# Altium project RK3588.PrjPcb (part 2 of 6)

## Sheet rk3588_LPDDR4.SchDoc
size C; SheetNumber: 3; SheetTotal: 22
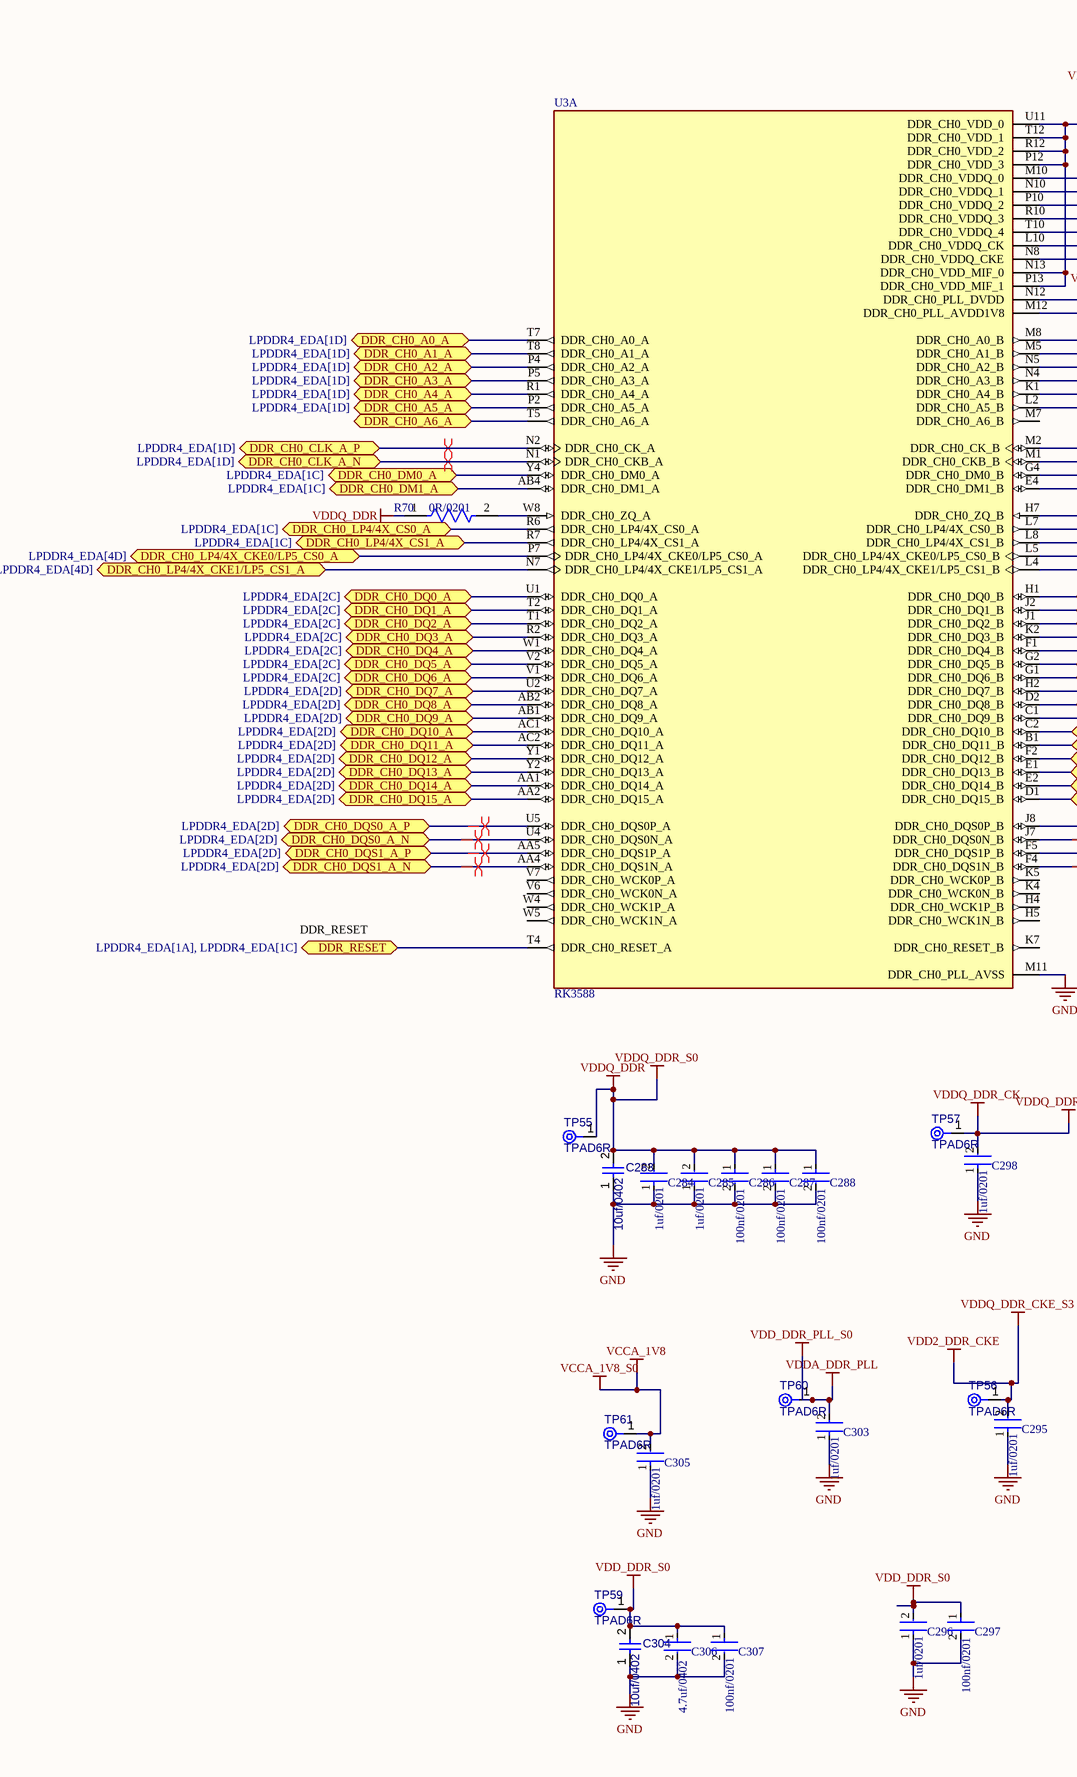
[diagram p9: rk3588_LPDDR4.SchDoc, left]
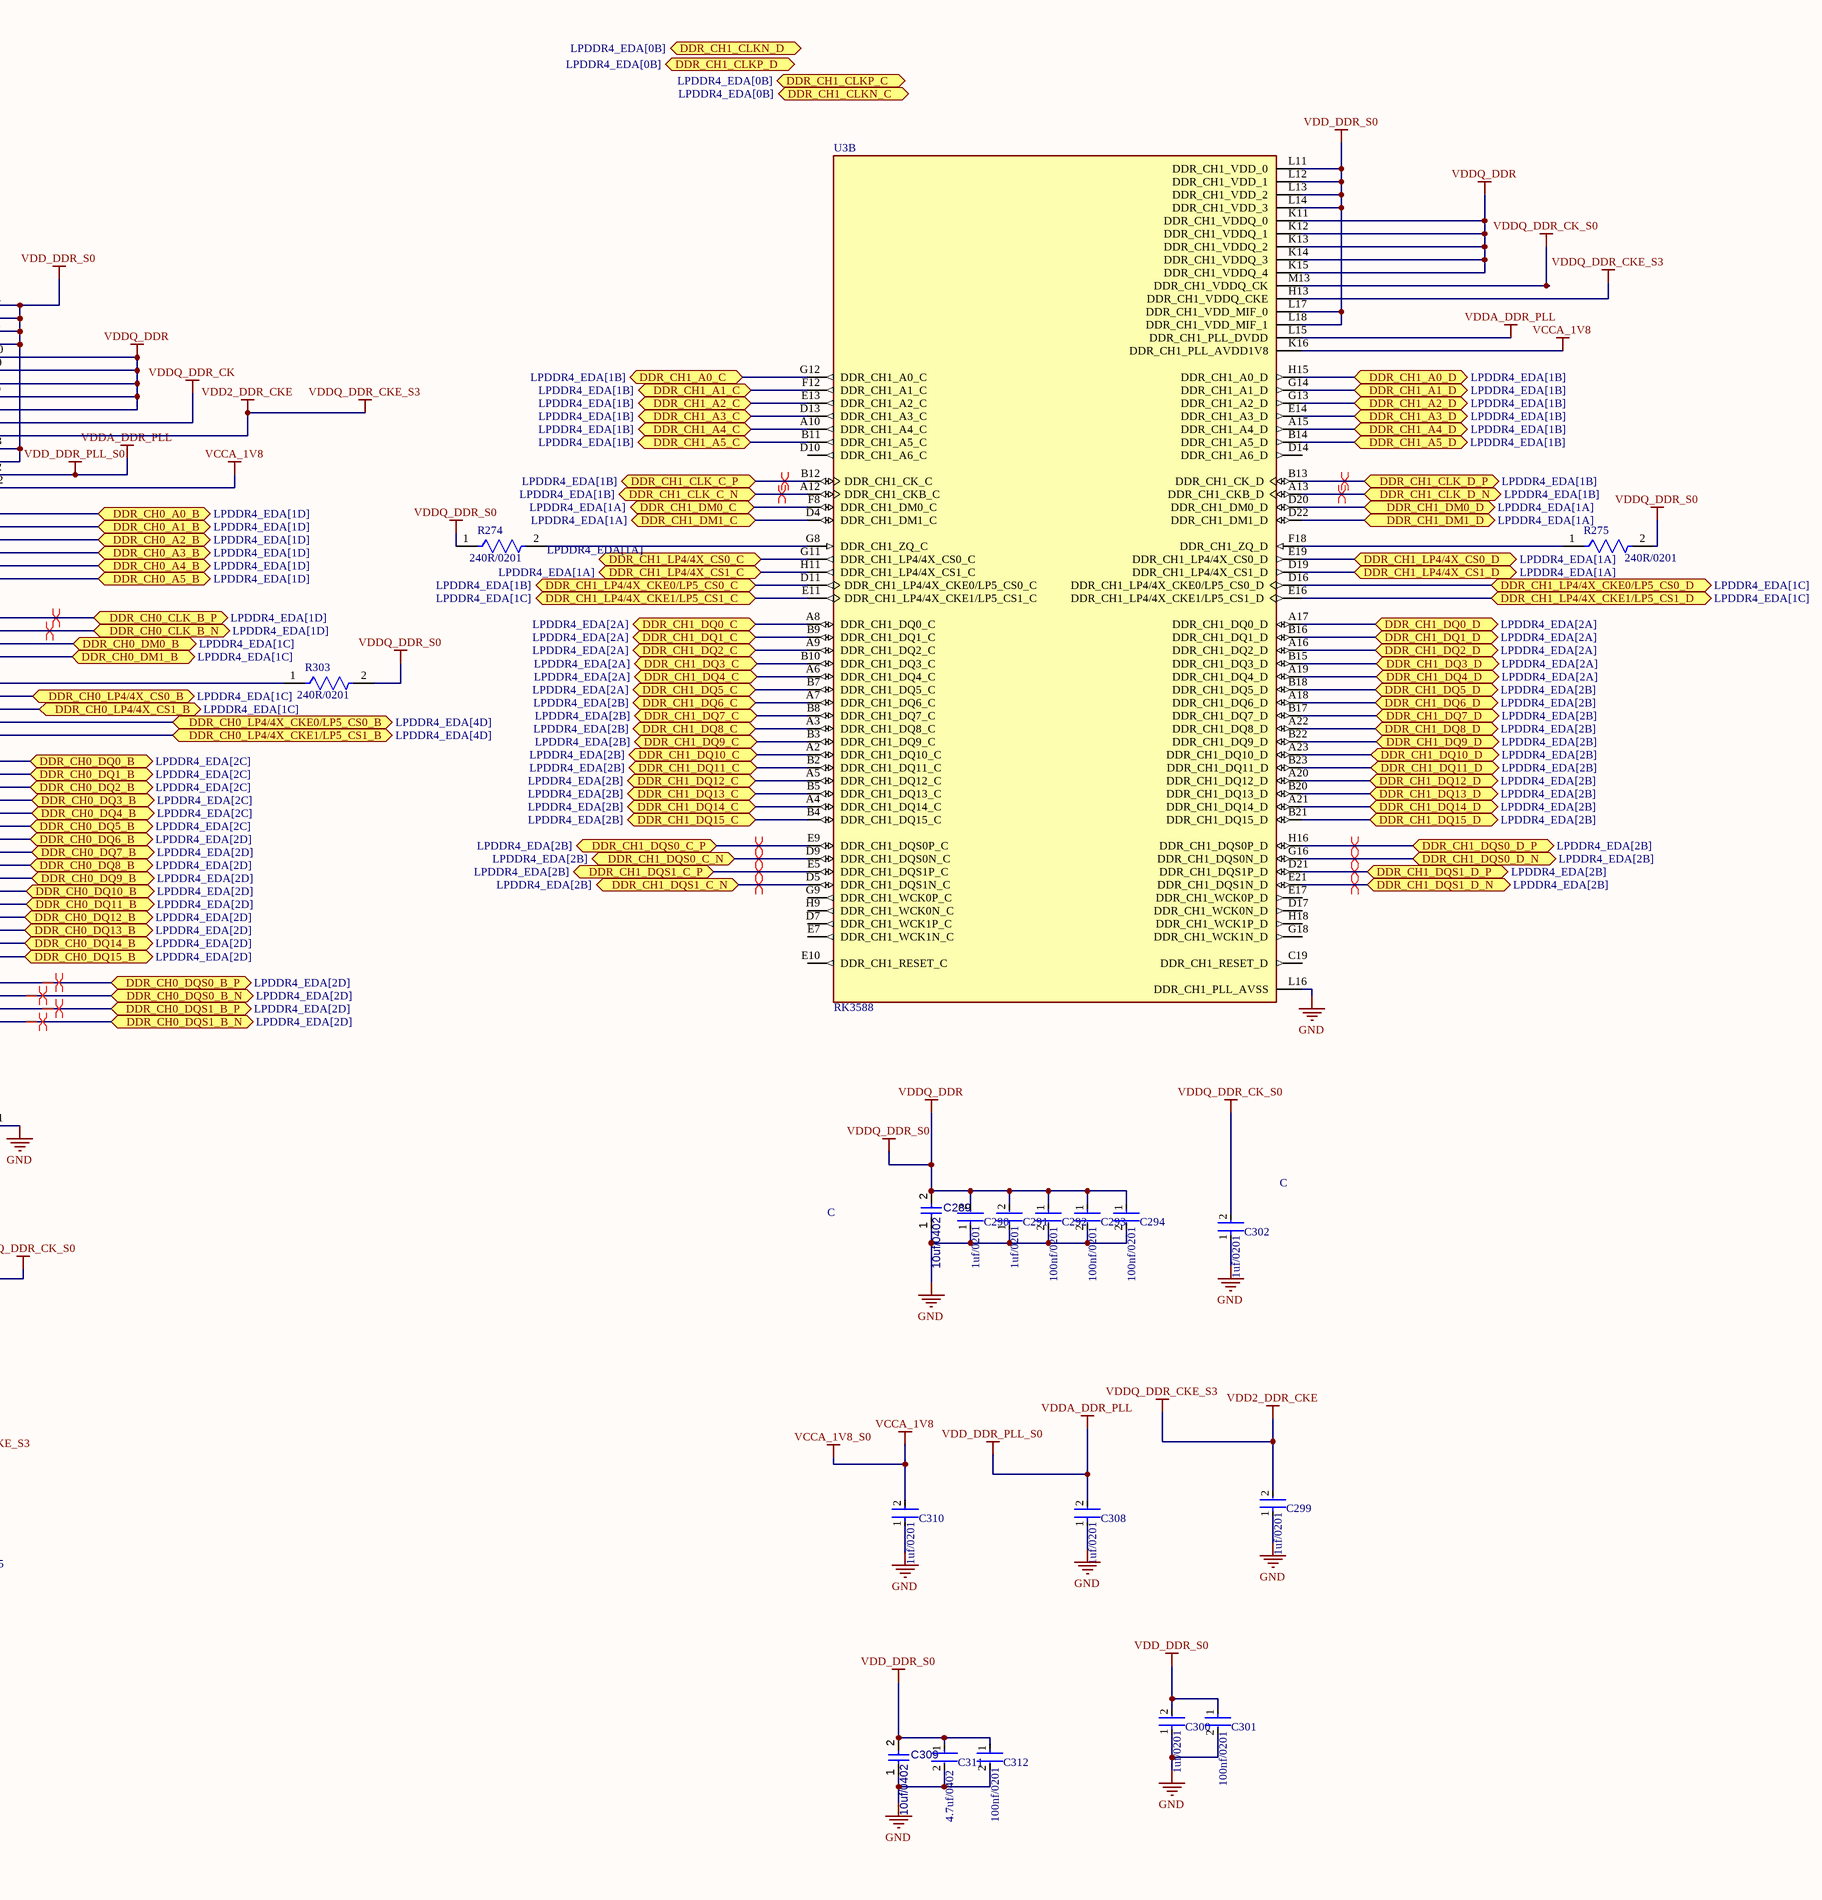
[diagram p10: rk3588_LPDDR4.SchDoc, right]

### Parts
C283  10uf/0402  [CAPC0402(1005)60_L]
C284  1uf/0201  [FP-CC0201-BA-MFG]
C285  1uf/0201  [FP-CC0201-BA-MFG]
C286  100nf/0201  [FP-CL03-IPC_C]
C287  100nf/0201  [FP-CL03-IPC_C]
C288  100nf/0201  [FP-CL03-IPC_C]
C289  10uf/0402  [CAPC0402(1005)60_L]
C290  1uf/0201  [FP-CC0201-BA-MFG]
C291  1uf/0201  [FP-CC0201-BA-MFG]
C292  100nf/0201  [FP-CL03-IPC_C]
C293  100nf/0201  [FP-CL03-IPC_C]
C294  100nf/0201  [FP-CL03-IPC_C]
C295  1uf/0201  [FP-CC0201-BA-MFG]
C296  1uf/0201  [FP-CC0201-BA-MFG]
C297  100nf/0201  [FP-CL03-IPC_C]
C298  1uf/0201  [FP-CC0201-BA-MFG]
C299  1uf/0201  [FP-CC0201-BA-MFG]
C300  1uf/0201  [FP-CC0201-BA-MFG]
C301  100nf/0201  [FP-CL03-IPC_C]
C302  1uf/0201  [FP-CC0201-BA-MFG]
C303  1uf/0201  [FP-CC0201-BA-MFG]
C304  10uf/0402  [CAPC0402(1005)60_L]
C305  1uf/0201  [FP-CC0201-BA-MFG]
C306  4.7uf/0402  [FP-CC0402-MFG]
C307  100nf/0201  [FP-CL03-IPC_C]
C308  1uf/0201  [FP-CC0201-BA-MFG]
C309  10uf/0402  [CAPC0402(1005)60_L]
C310  1uf/0201  [FP-CC0201-BA-MFG]
C311  4.7uf/0402  [FP-CC0402-MFG]
C312  100nf/0201  [FP-CL03-IPC_C]
R70  0R/0201  [FP-RMCF0201-IPC_C]
R274  240R/0201  [FP-RMCF0201-IPC_C]
R275  240R/0201  [FP-RMCF0201-IPC_C]
R303  240R/0201  [FP-RMCF0201-IPC_C]
TP55  TPAD6R  [TP06R]  (no BOM)
TP56  TPAD6R  [TP06R]  (no BOM)
TP57  TPAD6R  [TP06R]  (no BOM)
TP59  TPAD6R  [TP06R]  (no BOM)
TP60  TPAD6R  [TP06R]  (no BOM)
TP61  TPAD6R  [TP06R]  (no BOM)
U3  RK3588  [BGA1088C65P34X34_2300X2300X204N]  (parts A,B of 30)

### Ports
DDR_CH0_A0_A (bidir, see LPDDR4_EDA[1D]), DDR_CH0_A0_B (bidir, see LPDDR4_EDA[1D]), DDR_CH0_A1_A (bidir, see LPDDR4_EDA[1D]), DDR_CH0_A1_B (bidir, see LPDDR4_EDA[1D]), DDR_CH0_A2_A (bidir, see LPDDR4_EDA[1D]), DDR_CH0_A2_B (bidir, see LPDDR4_EDA[1D]), DDR_CH0_A3_A (bidir, see LPDDR4_EDA[1D]), DDR_CH0_A3_B (bidir, see LPDDR4_EDA[1D]), DDR_CH0_A4_A (bidir, see LPDDR4_EDA[1D]), DDR_CH0_A4_B (bidir, see LPDDR4_EDA[1D]), DDR_CH0_A5_A (bidir, see LPDDR4_EDA[1D]), DDR_CH0_A5_B (bidir, see LPDDR4_EDA[1D]), DDR_CH0_A6_A (bidir), DDR_CH0_CLK_A_N (bidir, see LPDDR4_EDA[1D]), DDR_CH0_CLK_A_P (bidir, see LPDDR4_EDA[1D]), DDR_CH0_CLK_B_N (bidir, see LPDDR4_EDA[1D]), DDR_CH0_CLK_B_P (bidir, see LPDDR4_EDA[1D]), DDR_CH0_DM0_A (bidir, see LPDDR4_EDA[1C]), DDR_CH0_DM0_B (bidir, see LPDDR4_EDA[1C]), DDR_CH0_DM1_A (bidir, see LPDDR4_EDA[1C]), DDR_CH0_DM1_B (bidir, see LPDDR4_EDA[1C]), DDR_CH0_DQ0_A (bidir, see LPDDR4_EDA[2C]), DDR_CH0_DQ0_B (bidir, see LPDDR4_EDA[2C]), DDR_CH0_DQ1_A (bidir, see LPDDR4_EDA[2C]), DDR_CH0_DQ1_B (bidir, see LPDDR4_EDA[2C]), DDR_CH0_DQ2_A (bidir, see LPDDR4_EDA[2C]), DDR_CH0_DQ2_B (bidir, see LPDDR4_EDA[2C]), DDR_CH0_DQ3_A (bidir, see LPDDR4_EDA[2C]), DDR_CH0_DQ3_B (bidir, see LPDDR4_EDA[2C]), DDR_CH0_DQ4_A (bidir, see LPDDR4_EDA[2C]), DDR_CH0_DQ4_B (bidir, see LPDDR4_EDA[2C]), DDR_CH0_DQ5_A (bidir, see LPDDR4_EDA[2C]), DDR_CH0_DQ5_B (bidir, see LPDDR4_EDA[2C]), DDR_CH0_DQ6_A (bidir, see LPDDR4_EDA[2C]), DDR_CH0_DQ6_B (bidir, see LPDDR4_EDA[2D]), DDR_CH0_DQ7_A (bidir, see LPDDR4_EDA[2D]), DDR_CH0_DQ7_B (bidir, see LPDDR4_EDA[2D]), DDR_CH0_DQ8_A (bidir, see LPDDR4_EDA[2D]), DDR_CH0_DQ8_B (bidir, see LPDDR4_EDA[2D]), DDR_CH0_DQ9_A (bidir, see LPDDR4_EDA[2D]), DDR_CH0_DQ9_B (bidir, see LPDDR4_EDA[2D]), DDR_CH0_DQ10_A (bidir, see LPDDR4_EDA[2D]), DDR_CH0_DQ10_B (bidir, see LPDDR4_EDA[2D]), DDR_CH0_DQ11_A (bidir, see LPDDR4_EDA[2D]), DDR_CH0_DQ11_B (bidir, see LPDDR4_EDA[2D]), DDR_CH0_DQ12_A (bidir, see LPDDR4_EDA[2D]), DDR_CH0_DQ12_B (bidir, see LPDDR4_EDA[2D]), DDR_CH0_DQ13_A (bidir, see LPDDR4_EDA[2D]), DDR_CH0_DQ13_B (bidir, see LPDDR4_EDA[2D]), DDR_CH0_DQ14_A (bidir, see LPDDR4_EDA[2D]), DDR_CH0_DQ14_B (bidir, see LPDDR4_EDA[2D]), DDR_CH0_DQ15_A (bidir, see LPDDR4_EDA[2D]), DDR_CH0_DQ15_B (bidir, see LPDDR4_EDA[2D]), DDR_CH0_DQS0_A_N (bidir, see LPDDR4_EDA[2D]), DDR_CH0_DQS0_A_P (bidir, see LPDDR4_EDA[2D]), DDR_CH0_DQS0_B_N (bidir, see LPDDR4_EDA[2D]), DDR_CH0_DQS0_B_P (bidir, see LPDDR4_EDA[2D]), DDR_CH0_DQS1_A_N (bidir, see LPDDR4_EDA[2D]), DDR_CH0_DQS1_A_P (bidir, see LPDDR4_EDA[2D]), DDR_CH0_DQS1_B_N (bidir, see LPDDR4_EDA[2D]), DDR_CH0_DQS1_B_P (bidir, see LPDDR4_EDA[2D]), DDR_CH0_LP4/4X_CKE0/LP5_CS0_A (bidir, see LPDDR4_EDA[4D]), DDR_CH0_LP4/4X_CKE0/LP5_CS0_B (bidir, see LPDDR4_EDA[4D]), DDR_CH0_LP4/4X_CKE1/LP5_CS1_A (bidir, see LPDDR4_EDA[4D]), DDR_CH0_LP4/4X_CKE1/LP5_CS1_B (bidir, see LPDDR4_EDA[4D]), DDR_CH0_LP4/4X_CS0_A (bidir, see LPDDR4_EDA[1C]), DDR_CH0_LP4/4X_CS0_B (bidir, see LPDDR4_EDA[1C]), DDR_CH0_LP4/4X_CS1_A (bidir, see LPDDR4_EDA[1C]), DDR_CH0_LP4/4X_CS1_B (bidir, see LPDDR4_EDA[1C]), DDR_CH1_A0_C (bidir, see LPDDR4_EDA[1B]), DDR_CH1_A0_D (bidir, see LPDDR4_EDA[1B]), DDR_CH1_A1_C (bidir, see LPDDR4_EDA[1B]), DDR_CH1_A1_D (bidir, see LPDDR4_EDA[1B]), DDR_CH1_A2_C (bidir, see LPDDR4_EDA[1B]), DDR_CH1_A2_D (bidir, see LPDDR4_EDA[1B]), DDR_CH1_A3_C (bidir, see LPDDR4_EDA[1B]), DDR_CH1_A3_D (bidir, see LPDDR4_EDA[1B]), DDR_CH1_A4_C (bidir, see LPDDR4_EDA[1B]), DDR_CH1_A4_D (bidir, see LPDDR4_EDA[1B]), DDR_CH1_A5_C (bidir, see LPDDR4_EDA[1B]), DDR_CH1_A5_D (bidir, see LPDDR4_EDA[1B]), DDR_CH1_CLK_C_N (bidir, see LPDDR4_EDA[1B]), DDR_CH1_CLK_C_P (bidir, see LPDDR4_EDA[1B]), DDR_CH1_CLK_D_N (bidir, see LPDDR4_EDA[1B]), DDR_CH1_CLK_D_P (bidir, see LPDDR4_EDA[1B]), DDR_CH1_CLKN_C (bidir, see LPDDR4_EDA[0B]), DDR_CH1_CLKN_D (bidir, see LPDDR4_EDA[0B]), DDR_CH1_CLKP_C (bidir, see LPDDR4_EDA[0B]), DDR_CH1_CLKP_D (bidir, see LPDDR4_EDA[0B]), DDR_CH1_DM0_C (bidir, see LPDDR4_EDA[1A]), DDR_CH1_DM0_D (bidir, see LPDDR4_EDA[1A]), DDR_CH1_DM1_C (bidir, see LPDDR4_EDA[1A]), DDR_CH1_DM1_D (bidir, see LPDDR4_EDA[1A]), DDR_CH1_DQ0_C (bidir, see LPDDR4_EDA[2A]), DDR_CH1_DQ0_D (bidir, see LPDDR4_EDA[2A]), DDR_CH1_DQ1_C (bidir, see LPDDR4_EDA[2A]), DDR_CH1_DQ1_D (bidir, see LPDDR4_EDA[2A]), DDR_CH1_DQ2_C (bidir, see LPDDR4_EDA[2A]), DDR_CH1_DQ2_D (bidir, see LPDDR4_EDA[2A]), DDR_CH1_DQ3_C (bidir, see LPDDR4_EDA[2A]), DDR_CH1_DQ3_D (bidir, see LPDDR4_EDA[2A]), DDR_CH1_DQ4_C (bidir, see LPDDR4_EDA[2A]), DDR_CH1_DQ4_D (bidir, see LPDDR4_EDA[2A]), DDR_CH1_DQ5_C (bidir, see LPDDR4_EDA[2A]), DDR_CH1_DQ5_D (bidir, see LPDDR4_EDA[2B]), DDR_CH1_DQ6_C (bidir, see LPDDR4_EDA[2B]), DDR_CH1_DQ6_D (bidir, see LPDDR4_EDA[2B]), DDR_CH1_DQ7_C (bidir, see LPDDR4_EDA[2B]), DDR_CH1_DQ7_D (bidir, see LPDDR4_EDA[2B]), DDR_CH1_DQ8_C (bidir, see LPDDR4_EDA[2B]), DDR_CH1_DQ8_D (bidir, see LPDDR4_EDA[2B]), DDR_CH1_DQ9_C (bidir, see LPDDR4_EDA[2B]), DDR_CH1_DQ9_D (bidir, see LPDDR4_EDA[2B]), DDR_CH1_DQ10_C (bidir, see LPDDR4_EDA[2B]), DDR_CH1_DQ10_D (bidir, see LPDDR4_EDA[2B]), DDR_CH1_DQ11_C (bidir, see LPDDR4_EDA[2B]), DDR_CH1_DQ11_D (bidir, see LPDDR4_EDA[2B]), DDR_CH1_DQ12_C (bidir, see LPDDR4_EDA[2B]), DDR_CH1_DQ12_D (bidir, see LPDDR4_EDA[2B]), DDR_CH1_DQ13_C (bidir, see LPDDR4_EDA[2B]), DDR_CH1_DQ13_D (bidir, see LPDDR4_EDA[2B]), DDR_CH1_DQ14_C (bidir, see LPDDR4_EDA[2B]), DDR_CH1_DQ14_D (bidir, see LPDDR4_EDA[2B]), DDR_CH1_DQ15_C (bidir, see LPDDR4_EDA[2B]), DDR_CH1_DQ15_D (bidir, see LPDDR4_EDA[2B]), DDR_CH1_DQS0_C_N (bidir, see LPDDR4_EDA[2B]), DDR_CH1_DQS0_C_P (bidir, see LPDDR4_EDA[2B]), DDR_CH1_DQS0_D_N (bidir, see LPDDR4_EDA[2B]), DDR_CH1_DQS0_D_P (bidir, see LPDDR4_EDA[2B]), DDR_CH1_DQS1_C_N (bidir, see LPDDR4_EDA[2B]), DDR_CH1_DQS1_C_P (bidir, see LPDDR4_EDA[2B]), DDR_CH1_DQS1_D_N (bidir, see LPDDR4_EDA[2B]), DDR_CH1_DQS1_D_P (bidir, see LPDDR4_EDA[2B]), DDR_CH1_LP4/4X_CKE0/LP5_CS0_C (bidir, see LPDDR4_EDA[1B]), DDR_CH1_LP4/4X_CKE0/LP5_CS0_D (bidir, see LPDDR4_EDA[1C]), DDR_CH1_LP4/4X_CKE1/LP5_CS1_C (bidir, see LPDDR4_EDA[1C]), DDR_CH1_LP4/4X_CKE1/LP5_CS1_D (bidir, see LPDDR4_EDA[1C]), DDR_CH1_LP4/4X_CS0_C (bidir, see LPDDR4_EDA[1A]), DDR_CH1_LP4/4X_CS0_D (bidir, see LPDDR4_EDA[1A]), DDR_CH1_LP4/4X_CS1_C (bidir, see LPDDR4_EDA[1A]), DDR_CH1_LP4/4X_CS1_D (bidir, see LPDDR4_EDA[1A]), DDR_RESET (bidir, see LPDDR4_EDA[1A], LPDDR4_EDA[1C])

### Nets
GND: C283.1 C284.1 C285.1 C286.2 C287.2 C288.2 C289.1 C290.1 C291.1 C292.2 C293.2 C294.2 C295.1 C296.1 C297.2 C298.1 C299.1 C300.1 C301.2 C302.1 C303.1 C304.1 C305.1 C306.2 C307.2 C308.1 C309.1 C310.1 C311.2 C312.2 U3.L16(DDR_CH1_PLL_AVSS) U3.M11(DDR_CH0_PLL_AVSS)
VCCA_1V8: C305.2 C310.2 TP61.1(TP) U3.K16(DDR_CH1_PLL_AVDD1V8) U3.M12(DDR_CH0_PLL_AVDD1V8)  [also labelled VCCA_1V8_S0]
VDD2_DDR_CKE: C295.2 C299.2 TP56.1(TP) U3.H13(DDR_CH1_VDDQ_CKE) U3.N8(DDR_CH0_VDDQ_CKE)  [also labelled VDDQ_DDR_CKE_S3]
VDD_DDR_PLL_S0: C303.2 C308.2 TP60.1(TP) U3.L15(DDR_CH1_PLL_DVDD) U3.N12(DDR_CH0_PLL_DVDD)  [also labelled VDDA_DDR_PLL]  [project net NLDO2]
VDD_DDR_S0: C296.2 C297.1 C300.2 C301.1 C304.2 C306.1 C307.1 C309.2 C311.1 C312.1 TP59.1(TP) U3.L11(DDR_CH1_VDD_0) U3.L12(DDR_CH1_VDD_1) U3.L13(DDR_CH1_VDD_2) U3.L14(DDR_CH1_VDD_3) U3.L17(DDR_CH1_VDD_MIF_0) U3.L18(DDR_CH1_VDD_MIF_1) U3.N13(DDR_CH0_VDD_MIF_0) U3.P12(DDR_CH0_VDD_3) U3.P13(DDR_CH0_VDD_MIF_1) U3.R12(DDR_CH0_VDD_2) U3.T12(DDR_CH0_VDD_1) U3.U11(DDR_CH0_VDD_0)
VDDQ_DDR: C283.2 C284.2 C285.2 C286.1 C287.1 C288.1 C289.2 C290.2 C291.2 C292.1 C293.1 C294.1 R70.1 R274.1 R275.2 R303.2 TP55.1(TP) U3.K11(DDR_CH1_VDDQ_0) U3.K12(DDR_CH1_VDDQ_1) U3.K13(DDR_CH1_VDDQ_2) U3.K14(DDR_CH1_VDDQ_3) U3.K15(DDR_CH1_VDDQ_4) U3.M10(DDR_CH0_VDDQ_0) U3.N10(DDR_CH0_VDDQ_1) U3.P10(DDR_CH0_VDDQ_2) U3.R10(DDR_CH0_VDDQ_3) U3.T10(DDR_CH0_VDDQ_4)  [also labelled VDDQ_DDR_S0]  [project net VOUT9]
VDDQ_DDR_CK: C298.2 C302.2 TP57.1(TP) U3.L10(DDR_CH0_VDDQ_CK) U3.M13(DDR_CH1_VDDQ_CK)  [also labelled VDDQ_DDR_CK_S0]
DDR_CH0_A0_A: U3.T7(DDR_CH0_A0_A) ; port DDR_CH0_A0_A
DDR_CH0_A0_B: U3.M8(DDR_CH0_A0_B) ; port DDR_CH0_A0_B
DDR_CH0_A1_A: U3.T8(DDR_CH0_A1_A) ; port DDR_CH0_A1_A
DDR_CH0_A1_B: U3.M5(DDR_CH0_A1_B) ; port DDR_CH0_A1_B
DDR_CH0_A2_A: U3.P4(DDR_CH0_A2_A) ; port DDR_CH0_A2_A
DDR_CH0_A2_B: U3.N5(DDR_CH0_A2_B) ; port DDR_CH0_A2_B
DDR_CH0_A3_A: U3.P5(DDR_CH0_A3_A) ; port DDR_CH0_A3_A
DDR_CH0_A3_B: U3.N4(DDR_CH0_A3_B) ; port DDR_CH0_A3_B
DDR_CH0_A4_A: U3.R1(DDR_CH0_A4_A) ; port DDR_CH0_A4_A
DDR_CH0_A4_B: U3.K1(DDR_CH0_A4_B) ; port DDR_CH0_A4_B
DDR_CH0_A5_A: U3.P2(DDR_CH0_A5_A) ; port DDR_CH0_A5_A
DDR_CH0_A5_B: U3.L2(DDR_CH0_A5_B) ; port DDR_CH0_A5_B
DDR_CH0_A6_A: U3.T5(DDR_CH0_A6_A) ; port DDR_CH0_A6_A
DDR_CH0_CLK_A_N: U3.N1(DDR_CH0_CKB_A) ; port DDR_CH0_CLK_A_N
DDR_CH0_CLK_A_P: U3.N2(DDR_CH0_CK_A) ; port DDR_CH0_CLK_A_P
DDR_CH0_CLK_B_N: U3.M1(DDR_CH0_CKB_B) ; port DDR_CH0_CLK_B_N
DDR_CH0_CLK_B_P: U3.M2(DDR_CH0_CK_B) ; port DDR_CH0_CLK_B_P
DDR_CH0_DM0_A: U3.Y4(DDR_CH0_DM0_A) ; port DDR_CH0_DM0_A
DDR_CH0_DM0_B: U3.G4(DDR_CH0_DM0_B) ; port DDR_CH0_DM0_B
DDR_CH0_DM1_A: U3.AB4(DDR_CH0_DM1_A) ; port DDR_CH0_DM1_A
DDR_CH0_DM1_B: U3.E4(DDR_CH0_DM1_B) ; port DDR_CH0_DM1_B
DDR_CH0_DQ0_A: U3.U1(DDR_CH0_DQ0_A) ; port DDR_CH0_DQ0_A
DDR_CH0_DQ0_B: U3.H1(DDR_CH0_DQ0_B) ; port DDR_CH0_DQ0_B
DDR_CH0_DQ1_A: U3.T2(DDR_CH0_DQ1_A) ; port DDR_CH0_DQ1_A
DDR_CH0_DQ1_B: U3.J2(DDR_CH0_DQ1_B) ; port DDR_CH0_DQ1_B
DDR_CH0_DQ2_A: U3.T1(DDR_CH0_DQ2_A) ; port DDR_CH0_DQ2_A
DDR_CH0_DQ2_B: U3.J1(DDR_CH0_DQ2_B) ; port DDR_CH0_DQ2_B
DDR_CH0_DQ3_A: U3.R2(DDR_CH0_DQ3_A) ; port DDR_CH0_DQ3_A
DDR_CH0_DQ3_B: U3.K2(DDR_CH0_DQ3_B) ; port DDR_CH0_DQ3_B
DDR_CH0_DQ4_A: U3.W1(DDR_CH0_DQ4_A) ; port DDR_CH0_DQ4_A
DDR_CH0_DQ4_B: U3.F1(DDR_CH0_DQ4_B) ; port DDR_CH0_DQ4_B
DDR_CH0_DQ5_A: U3.V2(DDR_CH0_DQ5_A) ; port DDR_CH0_DQ5_A
DDR_CH0_DQ5_B: U3.G2(DDR_CH0_DQ5_B) ; port DDR_CH0_DQ5_B
DDR_CH0_DQ6_A: U3.V1(DDR_CH0_DQ6_A) ; port DDR_CH0_DQ6_A
DDR_CH0_DQ6_B: U3.G1(DDR_CH0_DQ6_B) ; port DDR_CH0_DQ6_B
DDR_CH0_DQ7_A: U3.U2(DDR_CH0_DQ7_A) ; port DDR_CH0_DQ7_A
DDR_CH0_DQ7_B: U3.H2(DDR_CH0_DQ7_B) ; port DDR_CH0_DQ7_B
DDR_CH0_DQ8_A: U3.AB2(DDR_CH0_DQ8_A) ; port DDR_CH0_DQ8_A
DDR_CH0_DQ8_B: U3.D2(DDR_CH0_DQ8_B) ; port DDR_CH0_DQ8_B
DDR_CH0_DQ9_A: U3.AB1(DDR_CH0_DQ9_A) ; port DDR_CH0_DQ9_A
DDR_CH0_DQ9_B: U3.C1(DDR_CH0_DQ9_B) ; port DDR_CH0_DQ9_B
DDR_CH0_DQ10_A: U3.AC1(DDR_CH0_DQ10_A) ; port DDR_CH0_DQ10_A
DDR_CH0_DQ10_B: U3.C2(DDR_CH0_DQ10_B) ; port DDR_CH0_DQ10_B
DDR_CH0_DQ11_A: U3.AC2(DDR_CH0_DQ11_A) ; port DDR_CH0_DQ11_A
DDR_CH0_DQ11_B: U3.B1(DDR_CH0_DQ11_B) ; port DDR_CH0_DQ11_B
DDR_CH0_DQ12_A: U3.Y1(DDR_CH0_DQ12_A) ; port DDR_CH0_DQ12_A
DDR_CH0_DQ12_B: U3.F2(DDR_CH0_DQ12_B) ; port DDR_CH0_DQ12_B
DDR_CH0_DQ13_A: U3.Y2(DDR_CH0_DQ13_A) ; port DDR_CH0_DQ13_A
DDR_CH0_DQ13_B: U3.E1(DDR_CH0_DQ13_B) ; port DDR_CH0_DQ13_B
DDR_CH0_DQ14_A: U3.AA1(DDR_CH0_DQ14_A) ; port DDR_CH0_DQ14_A
DDR_CH0_DQ14_B: U3.E2(DDR_CH0_DQ14_B) ; port DDR_CH0_DQ14_B
DDR_CH0_DQ15_A: U3.AA2(DDR_CH0_DQ15_A) ; port DDR_CH0_DQ15_A
DDR_CH0_DQ15_B: U3.D1(DDR_CH0_DQ15_B) ; port DDR_CH0_DQ15_B
DDR_CH0_DQS0_A_N: U3.U4(DDR_CH0_DQS0N_A) ; port DDR_CH0_DQS0_A_N
DDR_CH0_DQS0_A_P: U3.U5(DDR_CH0_DQS0P_A) ; port DDR_CH0_DQS0_A_P
DDR_CH0_DQS0_B_N: U3.J7(DDR_CH0_DQS0N_B) ; port DDR_CH0_DQS0_B_N
DDR_CH0_DQS0_B_P: U3.J8(DDR_CH0_DQS0P_B) ; port DDR_CH0_DQS0_B_P
DDR_CH0_DQS1_A_N: U3.AA4(DDR_CH0_DQS1N_A) ; port DDR_CH0_DQS1_A_N
DDR_CH0_DQS1_A_P: U3.AA5(DDR_CH0_DQS1P_A) ; port DDR_CH0_DQS1_A_P
DDR_CH0_DQS1_B_N: U3.F4(DDR_CH0_DQS1N_B) ; port DDR_CH0_DQS1_B_N
DDR_CH0_DQS1_B_P: U3.F5(DDR_CH0_DQS1P_B) ; port DDR_CH0_DQS1_B_P
DDR_CH0_LP4/4X_CKE0/LP5_CS0_A: U3.P7(DDR_CH0_LP4/4X_CKE0/LP5_CS0_A) ; port DDR_CH0_LP4/4X_CKE0/LP5_CS0_A
DDR_CH0_LP4/4X_CKE0/LP5_CS0_B: U3.L5(DDR_CH0_LP4/4X_CKE0/LP5_CS0_B) ; port DDR_CH0_LP4/4X_CKE0/LP5_CS0_B
DDR_CH0_LP4/4X_CKE1/LP5_CS1_A: U3.N7(DDR_CH0_LP4/4X_CKE1/LP5_CS1_A) ; port DDR_CH0_LP4/4X_CKE1/LP5_CS1_A
DDR_CH0_LP4/4X_CKE1/LP5_CS1_B: U3.L4(DDR_CH0_LP4/4X_CKE1/LP5_CS1_B) ; port DDR_CH0_LP4/4X_CKE1/LP5_CS1_B
DDR_CH0_LP4/4X_CS0_A: U3.R6(DDR_CH0_LP4/4X_CS0_A) ; port DDR_CH0_LP4/4X_CS0_A
DDR_CH0_LP4/4X_CS0_B: U3.L7(DDR_CH0_LP4/4X_CS0_B) ; port DDR_CH0_LP4/4X_CS0_B
DDR_CH0_LP4/4X_CS1_A: U3.R7(DDR_CH0_LP4/4X_CS1_A) ; port DDR_CH0_LP4/4X_CS1_A
DDR_CH0_LP4/4X_CS1_B: U3.L8(DDR_CH0_LP4/4X_CS1_B) ; port DDR_CH0_LP4/4X_CS1_B
DDR_CH1_A0_C: U3.G12(DDR_CH1_A0_C) ; port DDR_CH1_A0_C
DDR_CH1_A0_D: U3.H15(DDR_CH1_A0_D) ; port DDR_CH1_A0_D
DDR_CH1_A1_C: U3.F12(DDR_CH1_A1_C) ; port DDR_CH1_A1_C
DDR_CH1_A1_D: U3.G14(DDR_CH1_A1_D) ; port DDR_CH1_A1_D
DDR_CH1_A2_C: U3.E13(DDR_CH1_A2_C) ; port DDR_CH1_A2_C
DDR_CH1_A2_D: U3.G13(DDR_CH1_A2_D) ; port DDR_CH1_A2_D
DDR_CH1_A3_C: U3.D13(DDR_CH1_A3_C) ; port DDR_CH1_A3_C
DDR_CH1_A3_D: U3.E14(DDR_CH1_A3_D) ; port DDR_CH1_A3_D
DDR_CH1_A4_C: U3.A10(DDR_CH1_A4_C) ; port DDR_CH1_A4_C
DDR_CH1_A4_D: U3.A15(DDR_CH1_A4_D) ; port DDR_CH1_A4_D
DDR_CH1_A5_C: U3.B11(DDR_CH1_A5_C) ; port DDR_CH1_A5_C
DDR_CH1_A5_D: U3.B14(DDR_CH1_A5_D) ; port DDR_CH1_A5_D
DDR_CH1_CLK_C_N: U3.A12(DDR_CH1_CKB_C) ; port DDR_CH1_CLK_C_N
DDR_CH1_CLK_C_P: U3.B12(DDR_CH1_CK_C) ; port DDR_CH1_CLK_C_P
DDR_CH1_CLK_D_N: U3.A13(DDR_CH1_CKB_D) ; port DDR_CH1_CLK_D_N
DDR_CH1_CLK_D_P: U3.B13(DDR_CH1_CK_D) ; port DDR_CH1_CLK_D_P
DDR_CH1_DM0_C: U3.F8(DDR_CH1_DM0_C) ; port DDR_CH1_DM0_C
DDR_CH1_DM0_D: U3.D20(DDR_CH1_DM0_D) ; port DDR_CH1_DM0_D
DDR_CH1_DM1_C: U3.D4(DDR_CH1_DM1_C) ; port DDR_CH1_DM1_C
DDR_CH1_DM1_D: U3.D22(DDR_CH1_DM1_D) ; port DDR_CH1_DM1_D
DDR_CH1_DQ0_C: U3.A8(DDR_CH1_DQ0_C) ; port DDR_CH1_DQ0_C
DDR_CH1_DQ0_D: U3.A17(DDR_CH1_DQ0_D) ; port DDR_CH1_DQ0_D
DDR_CH1_DQ1_C: U3.B9(DDR_CH1_DQ1_C) ; port DDR_CH1_DQ1_C
DDR_CH1_DQ1_D: U3.B16(DDR_CH1_DQ1_D) ; port DDR_CH1_DQ1_D
DDR_CH1_DQ2_C: U3.A9(DDR_CH1_DQ2_C) ; port DDR_CH1_DQ2_C
DDR_CH1_DQ2_D: U3.A16(DDR_CH1_DQ2_D) ; port DDR_CH1_DQ2_D
DDR_CH1_DQ3_C: U3.B10(DDR_CH1_DQ3_C) ; port DDR_CH1_DQ3_C
DDR_CH1_DQ3_D: U3.B15(DDR_CH1_DQ3_D) ; port DDR_CH1_DQ3_D
DDR_CH1_DQ4_C: U3.A6(DDR_CH1_DQ4_C) ; port DDR_CH1_DQ4_C
DDR_CH1_DQ4_D: U3.A19(DDR_CH1_DQ4_D) ; port DDR_CH1_DQ4_D
DDR_CH1_DQ5_C: U3.B7(DDR_CH1_DQ5_C) ; port DDR_CH1_DQ5_C
DDR_CH1_DQ5_D: U3.B18(DDR_CH1_DQ5_D) ; port DDR_CH1_DQ5_D
DDR_CH1_DQ6_C: U3.A7(DDR_CH1_DQ6_C) ; port DDR_CH1_DQ6_C
DDR_CH1_DQ6_D: U3.A18(DDR_CH1_DQ6_D) ; port DDR_CH1_DQ6_D
DDR_CH1_DQ7_C: U3.B8(DDR_CH1_DQ7_C) ; port DDR_CH1_DQ7_C
DDR_CH1_DQ7_D: U3.B17(DDR_CH1_DQ7_D) ; port DDR_CH1_DQ7_D
DDR_CH1_DQ8_C: U3.A3(DDR_CH1_DQ8_C) ; port DDR_CH1_DQ8_C
DDR_CH1_DQ8_D: U3.A22(DDR_CH1_DQ8_D) ; port DDR_CH1_DQ8_D
DDR_CH1_DQ9_C: U3.B3(DDR_CH1_DQ9_C) ; port DDR_CH1_DQ9_C
DDR_CH1_DQ9_D: U3.B22(DDR_CH1_DQ9_D) ; port DDR_CH1_DQ9_D
DDR_CH1_DQ10_C: U3.A2(DDR_CH1_DQ10_C) ; port DDR_CH1_DQ10_C
DDR_CH1_DQ10_D: U3.A23(DDR_CH1_DQ10_D) ; port DDR_CH1_DQ10_D
DDR_CH1_DQ11_C: U3.B2(DDR_CH1_DQ11_C) ; port DDR_CH1_DQ11_C
DDR_CH1_DQ11_D: U3.B23(DDR_CH1_DQ11_D) ; port DDR_CH1_DQ11_D
DDR_CH1_DQ12_C: U3.A5(DDR_CH1_DQ12_C) ; port DDR_CH1_DQ12_C
DDR_CH1_DQ12_D: U3.A20(DDR_CH1_DQ12_D) ; port DDR_CH1_DQ12_D
DDR_CH1_DQ13_C: U3.B5(DDR_CH1_DQ13_C) ; port DDR_CH1_DQ13_C
DDR_CH1_DQ13_D: U3.B20(DDR_CH1_DQ13_D) ; port DDR_CH1_DQ13_D
DDR_CH1_DQ14_C: U3.A4(DDR_CH1_DQ14_C) ; port DDR_CH1_DQ14_C
DDR_CH1_DQ14_D: U3.A21(DDR_CH1_DQ14_D) ; port DDR_CH1_DQ14_D
DDR_CH1_DQ15_C: U3.B4(DDR_CH1_DQ15_C) ; port DDR_CH1_DQ15_C
DDR_CH1_DQ15_D: U3.B21(DDR_CH1_DQ15_D) ; port DDR_CH1_DQ15_D
DDR_CH1_DQS0_C_N: U3.D9(DDR_CH1_DQS0N_C) ; port DDR_CH1_DQS0_C_N
DDR_CH1_DQS0_C_P: U3.E9(DDR_CH1_DQS0P_C) ; port DDR_CH1_DQS0_C_P
DDR_CH1_DQS0_D_N: U3.G16(DDR_CH1_DQS0N_D) ; port DDR_CH1_DQS0_D_N
DDR_CH1_DQS0_D_P: U3.H16(DDR_CH1_DQS0P_D) ; port DDR_CH1_DQS0_D_P
DDR_CH1_DQS1_C_N: U3.D5(DDR_CH1_DQS1N_C) ; port DDR_CH1_DQS1_C_N
DDR_CH1_DQS1_C_P: U3.E5(DDR_CH1_DQS1P_C) ; port DDR_CH1_DQS1_C_P
DDR_CH1_DQS1_D_N: U3.E21(DDR_CH1_DQS1N_D) ; port DDR_CH1_DQS1_D_N
DDR_CH1_DQS1_D_P: U3.D21(DDR_CH1_DQS1P_D) ; port DDR_CH1_DQS1_D_P
DDR_CH1_LP4/4X_CKE0/LP5_CS0_C: U3.D11(DDR_CH1_LP4/4X_CKE0/LP5_CS0_C) ; port DDR_CH1_LP4/4X_CKE0/LP5_CS0_C
DDR_CH1_LP4/4X_CKE0/LP5_CS0_D: U3.D16(DDR_CH1_LP4/4X_CKE0/LP5_CS0_D) ; port DDR_CH1_LP4/4X_CKE0/LP5_CS0_D
DDR_CH1_LP4/4X_CKE1/LP5_CS1_C: U3.E11(DDR_CH1_LP4/4X_CKE1/LP5_CS1_C) ; port DDR_CH1_LP4/4X_CKE1/LP5_CS1_C
DDR_CH1_LP4/4X_CKE1/LP5_CS1_D: U3.E16(DDR_CH1_LP4/4X_CKE1/LP5_CS1_D) ; port DDR_CH1_LP4/4X_CKE1/LP5_CS1_D
DDR_CH1_LP4/4X_CS0_C: U3.G11(DDR_CH1_LP4/4X_CS0_C) ; port DDR_CH1_LP4/4X_CS0_C
DDR_CH1_LP4/4X_CS0_D: U3.E19(DDR_CH1_LP4/4X_CS0_D) ; port DDR_CH1_LP4/4X_CS0_D
DDR_CH1_LP4/4X_CS1_C: U3.H11(DDR_CH1_LP4/4X_CS1_C) ; port DDR_CH1_LP4/4X_CS1_C
DDR_CH1_LP4/4X_CS1_D: U3.D19(DDR_CH1_LP4/4X_CS1_D) ; port DDR_CH1_LP4/4X_CS1_D
DDR_RESET: U3.T4(DDR_CH0_RESET_A) ; port DDR_RESET
NetR70_2: R70.2 U3.W8(DDR_CH0_ZQ_A)
NetR274_2: R274.2 U3.G8(DDR_CH1_ZQ_C)
NetR275_1: R275.1 U3.F18(DDR_CH1_ZQ_D)
NetR303_1: R303.1 U3.H7(DDR_CH0_ZQ_B)

Not connected (* = marked no-connect by the designer): U3 C19(DDR_CH1_RESET_D) D7(DDR_CH1_WCK1P_C) D10(DDR_CH1_A6_C) D14(DDR_CH1_A6_D) D17(DDR_CH1_WCK0N_D) E7(DDR_CH1_WCK1N_C) E10(DDR_CH1_RESET_C) E17(DDR_CH1_WCK0P_D) G9(DDR_CH1_WCK0P_C) G18(DDR_CH1_WCK1N_D) H4(DDR_CH0_WCK1P_B) H5(DDR_CH0_WCK1N_B) H9(DDR_CH1_WCK0N_C) H18(DDR_CH1_WCK1P_D) K4(DDR_CH0_WCK0N_B) K5(DDR_CH0_WCK0P_B) K7(DDR_CH0_RESET_B) M7(DDR_CH0_A6_B) V6(DDR_CH0_WCK0N_A) V7(DDR_CH0_WCK0P_A) W4(DDR_CH0_WCK1P_A) W5(DDR_CH0_WCK1N_A)

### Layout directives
differential pair; differential pair class RAM_80: DDR_CH0_CLK_A_N, DDR_CH0_CLK_A_P, DDR_CH0_CLK_B_N, DDR_CH0_CLK_B_P, DDR_CH0_DQS0_A_N, DDR_CH0_DQS0_A_P, DDR_CH0_DQS0_B_N, DDR_CH0_DQS0_B_P, DDR_CH0_DQS1_A_N, DDR_CH0_DQS1_A_P, DDR_CH0_DQS1_B_N, DDR_CH0_DQS1_B_P, DDR_CH1_CLK_C_N, DDR_CH1_CLK_C_P, DDR_CH1_CLK_D_N, DDR_CH1_CLK_D_P, DDR_CH1_DQS0_C_N, DDR_CH1_DQS0_C_P, DDR_CH1_DQS0_D_N, DDR_CH1_DQS0_D_P, DDR_CH1_DQS1_C_N, DDR_CH1_DQS1_C_P, DDR_CH1_DQS1_D_N, DDR_CH1_DQS1_D_P

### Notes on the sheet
- DDR_RESET
- C

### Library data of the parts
C283 C289 C304 C309 = CMP-001-00074-3: 10uF 6.3V X5R ±20% 0402 Multilayer Ceramic Capacitors MLCC - SMD/SMT ROHS; Value: 10µF; Tolerance: 10%; MN: GRM155R60J106ME44D
C284 C285 C290 C291 C295 C296 C298-C300 C302 C303 C305 C308 C310 = CMP-03422-000660-2: 1uF 6.3V X5R ±20% 0201 Multilayer Ceramic Capacitors MLCC - SMD/SMT ROHS; Manufacturer: Yageo; Manufacturer Part Number: CC0201MRX5R5BB105; Tolerance: 0.2; Temperature Coefficient: 15%; MN: CL03A105MQ3CSNH
C286-C288 C292-C294 C297 C301 C307 C312 = CMP-2010-00672-2: Cap Ceramic 100nF 10V X5R ±10% Pad SMD 0201 +85°C T/R; MN: CL03A104KP3NNNC
C306 C311 = CMP-03422-000823-1: 10V 4.7uF X5R ±10% 0402 Multilayer Ceramic Capacitors MLCC - SMD/SMT ROHS; Manufacturer Part Number: CC0402KRX5R6BB475; Manufacturer: YAGEO; Automotive Grade: NA; Temperature Coefficient: 30ppm/°C; Tolerance: 0.1
R70 = CMP-26527-001890-1: -55℃~+155℃ 0Ω 25V 50mW Thick Film Resistor 0201 Chip Resistor - Surface Mount ROHS; Resistance: 0R; MN: RMCF0201ZT0R00
R274 R275 R303 = CMP-26527-006303-1: 240Ω ±1% 0.05W 0201 Thick Film Chip Resistor AEC-Q200 compliant; Temperature Coefficient: 200ppm/°C; Resistance: 240R; Max Power Dissipation: 50mW
TP55-TP57 TP59-TP61 = CMP-00028-00002-2: 0.6mm round
U3 = RK3588: low power, high performance processor; MF: Fuzhou Rockchip Electronics Co

## Sheet RK806-1.SchDoc
size A2; SheetNumber: 4; SheetTotal: 22
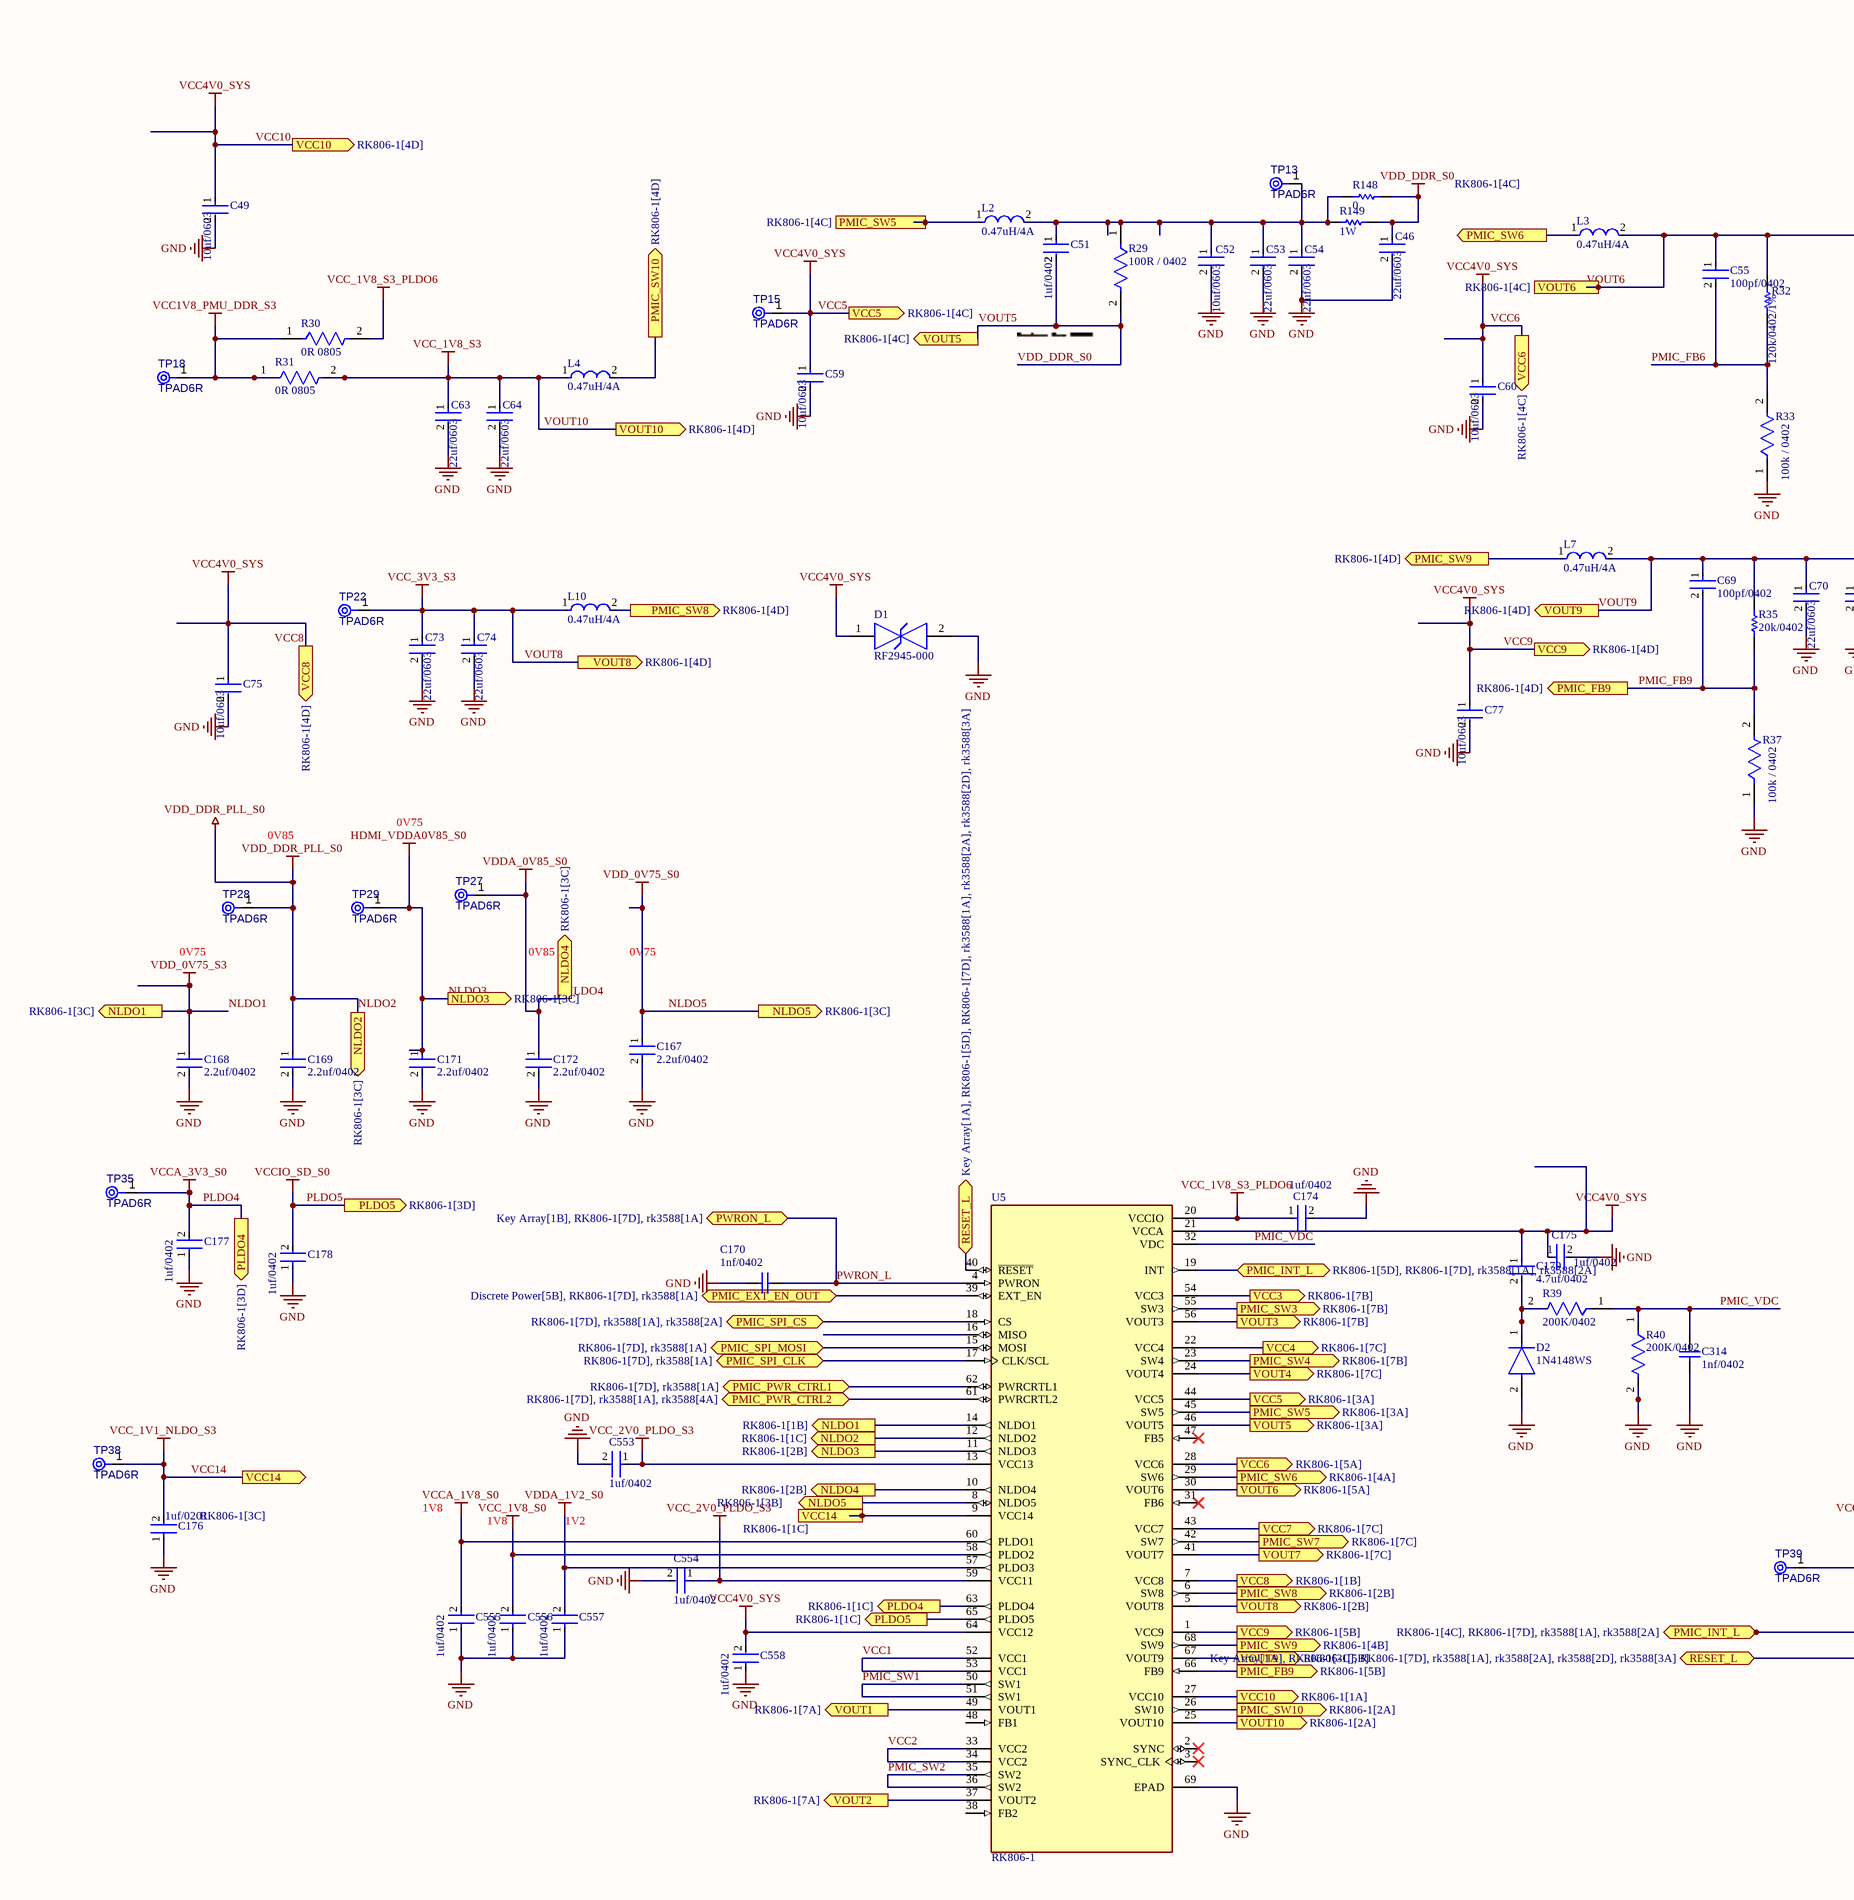
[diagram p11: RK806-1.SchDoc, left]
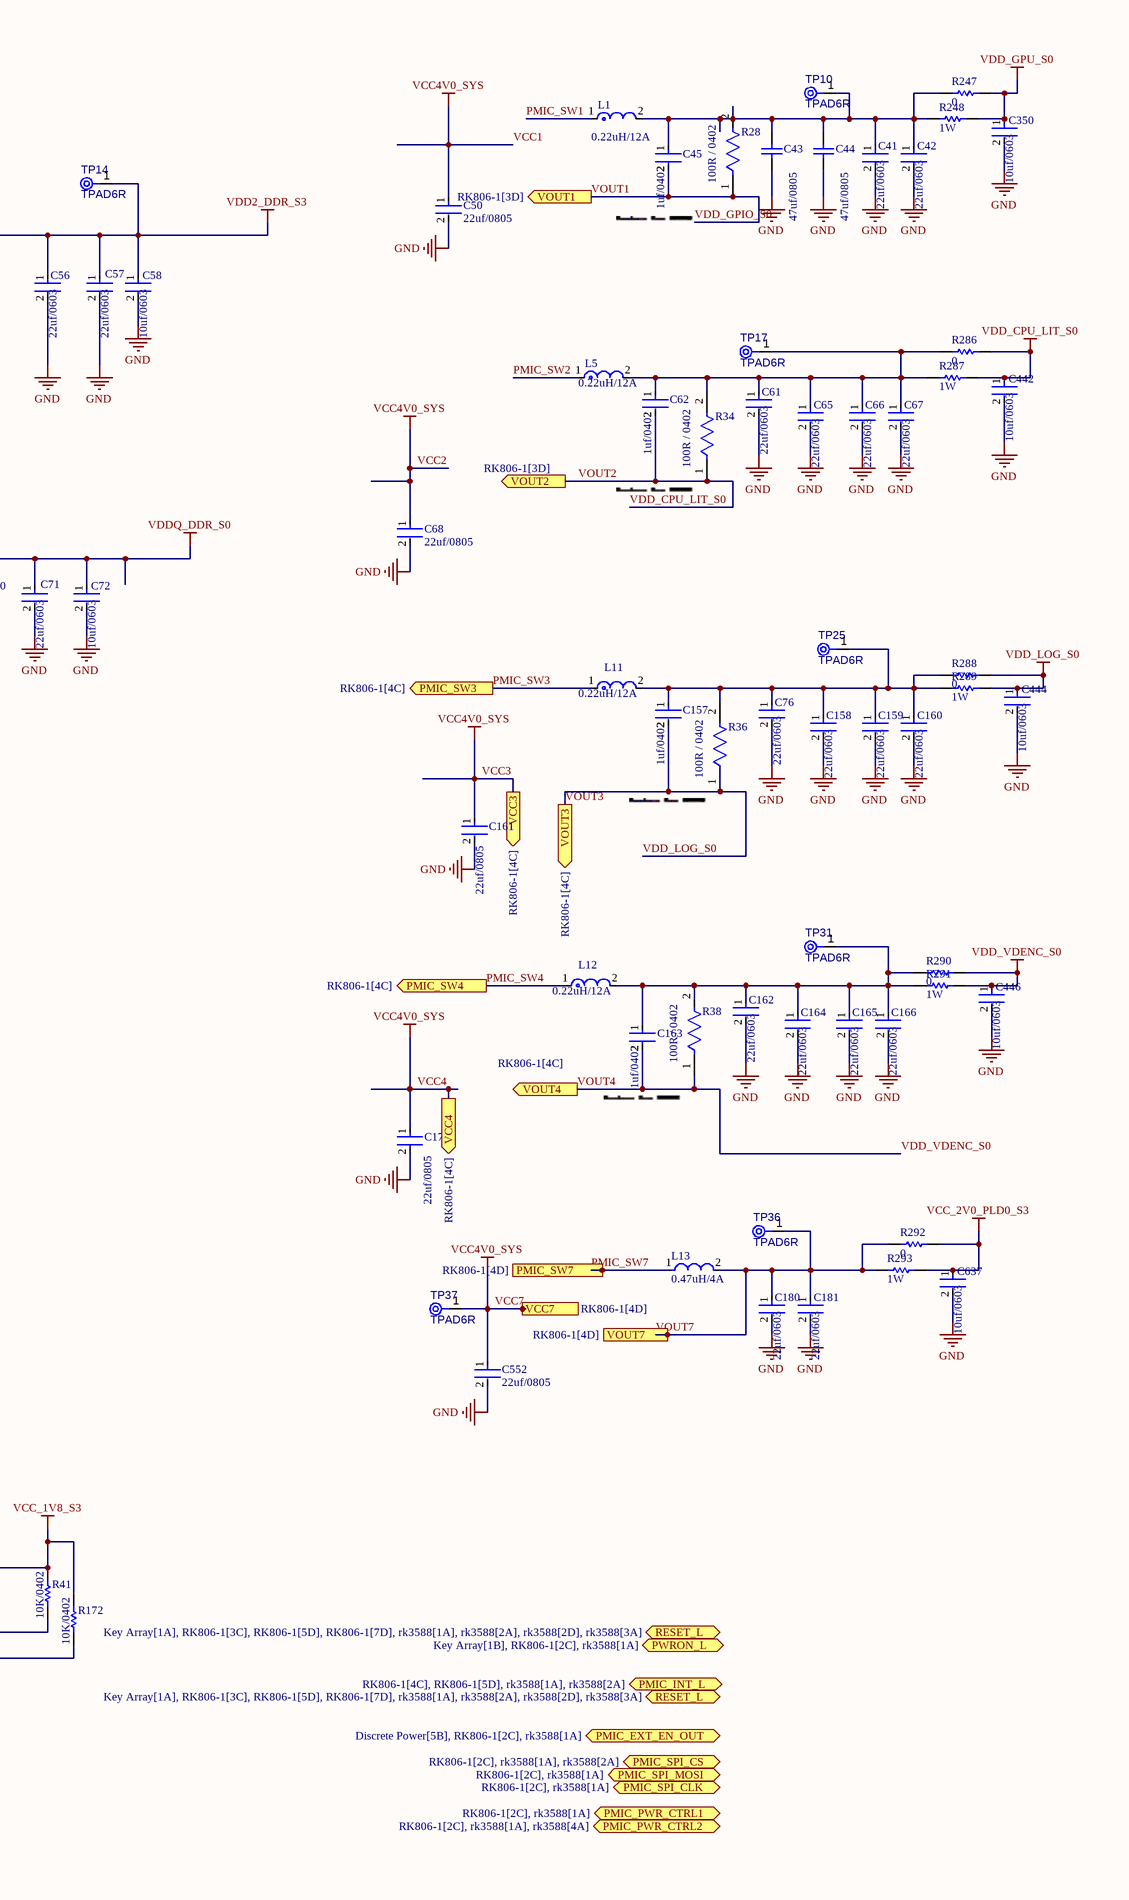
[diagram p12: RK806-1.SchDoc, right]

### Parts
C41  22uf/0603  [FP-GRM186-0_2-MFG]
C42  22uf/0603  [FP-GRM186-0_2-MFG]
C43  47uf/0805  [CAPC2013X145X50ML20T25]
C44  47uf/0805  [CAPC2013X145X50ML20T25]
C45  1uf/0402  [FP-C0402C105K8PACTU-MFG]
C46  22uf/0603  [FP-GRM186-0_2-MFG]
C49  10uf/0603  [FP-CC0603-DC-MFG]
C50  22uf/0805  [FP-C0805C226M8PACTU-MFG]
C51  1uf/0402  [FP-C0402C105K8PACTU-MFG]
C52  10uf/0603  [FP-CC0603-DC-MFG]
C53  22uf/0603  [FP-GRM186-0_2-MFG]
C54  22uf/0603  [FP-GRM186-0_2-MFG]
C55  100pf/0402  [FP-C0402-BB-MFG]
C56  22uf/0603  [FP-GRM186-0_2-MFG]
C57  22uf/0603  [FP-GRM186-0_2-MFG]
C58  10uf/0603  [FP-CC0603-DC-MFG]
C59  10uf/0603  [FP-CC0603-DC-MFG]
C60  10uf/0603  [FP-CC0603-DC-MFG]
C61  22uf/0603  [FP-GRM186-0_2-MFG]
C62  1uf/0402  [FP-C0402C105K8PACTU-MFG]
C63  22uf/0603  [FP-GRM186-0_2-MFG]
C64  22uf/0603  [FP-GRM186-0_2-MFG]
C65  22uf/0603  [FP-GRM186-0_2-MFG]
C66  22uf/0603  [FP-GRM186-0_2-MFG]
C67  22uf/0603  [FP-GRM186-0_2-MFG]
C68  22uf/0805  [FP-C0805C226M8PACTU-MFG]
C69  100pf/0402  [FP-C0402-BB-MFG]
C70  22uf/0603  [FP-GRM186-0_2-MFG]
C71  22uf/0603  [FP-GRM186-0_2-MFG]
C72  10uf/0603  [FP-CC0603-DC-MFG]
C73  22uf/0603  [FP-GRM186-0_2-MFG]
C74  22uf/0603  [FP-GRM186-0_2-MFG]
C75  10uf/0603  [FP-CC0603-DC-MFG]
C76  22uf/0603  [FP-GRM186-0_2-MFG]
C77  10uf/0603  [FP-CC0603-DC-MFG]
C157  1uf/0402  [FP-C0402C105K8PACTU-MFG]
C158  22uf/0603  [FP-GRM186-0_2-MFG]
C159  22uf/0603  [FP-GRM186-0_2-MFG]
C160  22uf/0603  [FP-GRM186-0_2-MFG]
C161  22uf/0805  [FP-C0805C226M8PACTU-MFG]
C162  22uf/0603  [FP-GRM186-0_2-MFG]
C163  1uf/0402  [FP-C0402C105K8PACTU-MFG]
C164  22uf/0603  [FP-GRM186-0_2-MFG]
C165  22uf/0603  [FP-GRM186-0_2-MFG]
C166  22uf/0603  [FP-GRM186-0_2-MFG]
C167  2.2uf/0402  [FP-CC0402-CC-MFG]
C168  2.2uf/0402  [FP-CC0402-CC-MFG]
C169  2.2uf/0402  [FP-CC0402-CC-MFG]
C170  1nf/0402  [CAPC1005X55X25LL05T05]
C171  2.2uf/0402  [FP-CC0402-CC-MFG]
C172  2.2uf/0402  [FP-CC0402-CC-MFG]
C173  22uf/0805  [FP-C0805C226M8PACTU-MFG]
C174  1uf/0402  [FP-C0402C105K8PACTU-MFG]
C175  1uf/0402  [FP-C0402C105K8PACTU-MFG]
C176  1uf/0201  [FP-CC0201-BA-MFG]
C177  1uf/0402  [FP-C0402C105K8PACTU-MFG]
C178  1uf/0402  [FP-C0402C105K8PACTU-MFG]
C179  4.7uf/0402  [FP-CC0402-MFG]
C180  22uf/0603  [FP-GRM186-0_2-MFG]
C181  22uf/0603  [FP-GRM186-0_2-MFG]
C314  1nf/0402  [CAPC1005X55X25LL05T05]
C350  10uf/0603  [FP-CC0603-DC-MFG]
C442  10uf/0603  [FP-CC0603-DC-MFG]
C444  10uf/0603  [FP-CC0603-DC-MFG]
C446  10uf/0603  [FP-CC0603-DC-MFG]
C552  22uf/0805  [FP-C0805C226M8PACTU-MFG]
C553  1uf/0402  [FP-C0402C105K8PACTU-MFG]
C554  1uf/0402  [FP-C0402C105K8PACTU-MFG]
C555  1uf/0402  [FP-C0402C105K8PACTU-MFG]
C556  1uf/0402  [FP-C0402C105K8PACTU-MFG]
C557  1uf/0402  [FP-C0402C105K8PACTU-MFG]
C558  1uf/0402  [FP-C0402C105K8PACTU-MFG]
C637  10uf/0603  [FP-CC0603-DC-MFG]
D1  RF2945-000  [FP-SESD0402-MFG]
D2  1N4148WS  [FP-477AB-IPC_C]
L1  0.22uH/12A  [FP-FDSD0415-MFG]
L2  0.47uH/4A  [FP-NRS5030-H_3_1-MFG]
L3  0.47uH/4A  [FP-NRS5030-H_3_1-MFG]
L4  0.47uH/4A  [FP-NRS5030-H_3_1-MFG]
L5  0.22uH/12A  [FP-FDSD0415-MFG]
L7  0.47uH/4A  [FP-NRS5030-H_3_1-MFG]
L10  0.47uH/4A  [FP-NRS5030-H_3_1-MFG]
L11  0.22uH/12A  [FP-FDSD0415-MFG]
L12  0.22uH/12A  [FP-FDSD0415-MFG]
L13  0.47uH/4A  [FP-NRS5030-H_3_1-MFG]
R28  100R / 0402  [FP-MCS0402-IPC_C]
R29  100R / 0402  [FP-MCS0402-IPC_C]
R30  0R 0805  [FP-AF0805-IPC_B]
R31  0R 0805  [FP-AF0805-IPC_B]
R32  120k/0402/1%  [RESC1005X40X25ML05T10]
R33  100k / 0402  [FP-CRGP0402-IPC_C]
R34  100R / 0402  [FP-MCS0402-IPC_C]
R35  20k/0402  [RESC1005X40X25ML10T10]
R36  100R / 0402  [FP-MCS0402-IPC_C]
R37  100k / 0402  [FP-CRGP0402-IPC_C]
R38  100R / 0402  [FP-MCS0402-IPC_C]
R39  200K/0402  [FP-AC0402-IPC_B]
R40  200K/0402  [FP-AC0402-IPC_B]
R41  10K/0402  [RESC1005X40X20NL05T10]
R148  value 0  [RESC3216X60X45ML15T20]  (hidden comment: Resistor 0R +/- 5% 1206 250 mW)
R149  value 1W  [RESC3216X60X45ML15T20]  (hidden comment: HoYH1206-1W-10mR-1%)
R172  10K/0402  [RESC1005X40X20NL05T10]
R247  value 0  [RESC3216X60X45ML15T20]  (hidden comment: Resistor 0R +/- 5% 1206 250 mW)
R248  value 1W  [RESC3216X60X45ML15T20]  (hidden comment: HoYH1206-1W-10mR-1%)
R286  value 0  [RESC3216X60X45ML15T20]  (hidden comment: Resistor 0R +/- 5% 1206 250 mW)
R287  value 1W  [RESC3216X60X45ML15T20]  (hidden comment: HoYH1206-1W-10mR-1%)
R288  value 0  [RESC3216X60X45ML15T20]  (hidden comment: Resistor 0R +/- 5% 1206 250 mW)
R289  value 1W  [RESC3216X60X45ML15T20]  (hidden comment: HoYH1206-1W-10mR-1%)
R290  value 0  [RESC3216X60X45ML15T20]  (hidden comment: Resistor 0R +/- 5% 1206 250 mW)
R291  value 1W  [RESC3216X60X45ML15T20]  (hidden comment: HoYH1206-1W-10mR-1%)
R292  value 0  [RESC3216X60X45ML15T20]  (hidden comment: Resistor 0R +/- 5% 1206 250 mW)
R293  value 1W  [RESC3216X60X45ML15T20]  (hidden comment: HoYH1206-1W-10mR-1%)
TP10  TPAD6R  [TP06R]  (no BOM)
TP13  TPAD6R  [TP06R]  (no BOM)
TP14  TPAD6R  [TP06R]  (no BOM)
TP15  TPAD6R  [TP06R]  (no BOM)
TP17  TPAD6R  [TP06R]  (no BOM)
TP18  TPAD6R  [TP06R]  (no BOM)
TP22  TPAD6R  [TP06R]  (no BOM)
TP25  TPAD6R  [TP06R]  (no BOM)
TP27  TPAD6R  [TP06R]  (no BOM)
TP28  TPAD6R  [TP06R]  (no BOM)
TP29  TPAD6R  [TP06R]  (no BOM)
TP31  TPAD6R  [TP06R]  (no BOM)
TP35  TPAD6R  [TP06R]  (no BOM)
TP36  TPAD6R  [TP06R]  (no BOM)
TP37  TPAD6R  [TP06R]  (no BOM)
TP38  TPAD6R  [TP06R]  (no BOM)
TP39  TPAD6R  [TP06R]  (no BOM)
U5  RK806-1  [QFN35P700X700X90-69N]

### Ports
NLDO1 (out, see RK806-1[1B]), NLDO1 (out, see RK806-1[3C]), NLDO2 (out, see RK806-1[1C]), NLDO2 (out, see RK806-1[3C]), NLDO3 (out, see RK806-1[2B]), NLDO3 (out, see RK806-1[3C]), NLDO4 (out, see RK806-1[2B]), NLDO4 (out, see RK806-1[3C]), NLDO5 (out, see RK806-1[3B]), NLDO5 (out, see RK806-1[3C]), PLDO4 (out, see RK806-1[1C]), PLDO4 (out, see RK806-1[3D]), PLDO5 (out, see RK806-1[1C]), PLDO5 (out, see RK806-1[3D]), PMIC_EXT_EN_OUT (bidir, see Discrete Power[5B], RK806-1[2C], rk3588[1A]), PMIC_EXT_EN_OUT (bidir, see Discrete Power[5B], RK806-1[7D], rk3588[1A]), PMIC_FB9 (out, see RK806-1[4D]), PMIC_FB9 (out, see RK806-1[5B]), PMIC_INT_L (bidir, see RK806-1[4C], RK806-1[5D], rk3588[1A], rk3588[2A]), PMIC_INT_L (bidir, see RK806-1[4C], RK806-1[7D], rk3588[1A], rk3588[2A]), PMIC_INT_L (bidir, see RK806-1[5D], RK806-1[7D], rk3588[1A], rk3588[2A]), PMIC_PWR_CTRL1 (bidir, see RK806-1[2C], rk3588[1A]), PMIC_PWR_CTRL1 (bidir, see RK806-1[7D], rk3588[1A]), PMIC_PWR_CTRL2 (bidir, see RK806-1[2C], rk3588[1A], rk3588[4A]), PMIC_PWR_CTRL2 (bidir, see RK806-1[7D], rk3588[1A], rk3588[4A]), PMIC_SPI_CLK (bidir, see RK806-1[2C], rk3588[1A]), PMIC_SPI_CLK (bidir, see RK806-1[7D], rk3588[1A]), PMIC_SPI_CS (bidir, see RK806-1[2C], rk3588[1A], rk3588[2A]), PMIC_SPI_CS (bidir, see RK806-1[7D], rk3588[1A], rk3588[2A]), PMIC_SPI_MOSI (bidir, see RK806-1[2C], rk3588[1A]), PMIC_SPI_MOSI (bidir, see RK806-1[7D], rk3588[1A]), PMIC_SW3 (out, see RK806-1[4C]), PMIC_SW3 (out, see RK806-1[7B]), PMIC_SW4 (out, see RK806-1[4C]), PMIC_SW4 (out, see RK806-1[7B]), PMIC_SW5 (out, see RK806-1[3A]), PMIC_SW5 (out, see RK806-1[4C]), PMIC_SW6 (out, see RK806-1[4A]), PMIC_SW6 (out, see RK806-1[4C]), PMIC_SW7 (out, see RK806-1[4D]), PMIC_SW7 (out, see RK806-1[7C]), PMIC_SW8 (out, see RK806-1[2B]), PMIC_SW8 (out, see RK806-1[4D]), PMIC_SW9 (out, see RK806-1[4B]), PMIC_SW9 (out, see RK806-1[4D]), PMIC_SW10 (out, see RK806-1[2A]), PMIC_SW10 (out, see RK806-1[4D]), PWRON_L (bidir, see Key Array[1B], RK806-1[2C], rk3588[1A]), PWRON_L (bidir, see Key Array[1B], RK806-1[7D], rk3588[1A]), RESET_L (bidir, see Key Array[1A], RK806-1[3C], RK806-1[5D], RK806-1[7D], rk3588[1A], rk3588[2A], rk3588[2D], rk3588[3A]), RESET_L (bidir, see Key Array[1A], RK806-1[3C], RK806-1[7D], rk3588[1A], rk3588[2A], rk3588[2D], rk3588[3A]), RESET_L (bidir, see Key Array[1A], RK806-1[5D], RK806-1[7D], rk3588[1A], rk3588[2A], rk3588[2D], rk3588[3A]), VCC3 (out, see RK806-1[4C]), VCC3 (out, see RK806-1[7B]), VCC4 (out, see RK806-1[4C]), VCC4 (out, see RK806-1[7C]), VCC5 (out, see RK806-1[3A]), VCC5 (out, see RK806-1[4C]), VCC6 (out, see RK806-1[4C]), VCC6 (out, see RK806-1[5A]), VCC7 (out, see RK806-1[4D]), VCC7 (out, see RK806-1[7C]), VCC8 (out, see RK806-1[1B]), VCC8 (out, see RK806-1[4D]), VCC9 (out, see RK806-1[4D]), VCC9 (out, see RK806-1[5B]), VCC10 (out, see RK806-1[1A]), VCC10 (out, see RK806-1[4D]), VCC14 (out, see RK806-1[1C]), VCC14 (out, see RK806-1[3C]), VOUT1 (out, see RK806-1[3D]), VOUT1 (out, see RK806-1[7A]), VOUT2 (out, see RK806-1[3D]), VOUT2 (out, see RK806-1[7A]), VOUT3 (out, see RK806-1[4C]), VOUT3 (out, see RK806-1[7B]), VOUT4 (out, see RK806-1[4C]), VOUT4 (out, see RK806-1[7C]), VOUT5 (out, see RK806-1[3A]), VOUT5 (out, see RK806-1[4C]), VOUT6 (out, see RK806-1[4C]), VOUT6 (out, see RK806-1[5A]), VOUT7 (out, see RK806-1[4D]), VOUT7 (out, see RK806-1[7C]), VOUT8 (out, see RK806-1[2B]), VOUT8 (out, see RK806-1[4D]), VOUT9 (out, see RK806-1[4D]), VOUT9 (out, see RK806-1[5B]), VOUT10 (out, see RK806-1[2A]), VOUT10 (out, see RK806-1[4D])

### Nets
GND: C41.2 C42.2 C43.1 C44.1 C46.2 C49.2 C50.2 C52.2 C53.2 C54.2 C56.2 C57.2 C58.2 C59.2 C60.2 C61.2 C63.2 C64.2 C65.2 C66.2 C67.2 C68.2 C70.2 C71.2 C72.2 C73.2 C74.2 C75.2 C76.2 C77.2 C158.2 C159.2 C160.2 C161.2 C162.2 C164.2 C165.2 C166.2 C167.2 C168.2 C169.2 C170.1 C171.2 C172.2 C173.2 C174.2 C175.2 C176.1 C177.1 C178.1 C180.2 C181.2 C314.1 C350.2 C442.2 C444.2 C446.2 C552.2 C553.2 C554.2 C555.1 C556.1 C557.1 C558.1 C637.2 D1.2 D2.2(A) R33.1 R37.1 R40.2 U5.69(EPAD)
NLDO1: C168.1 U5.14(NLDO1) ; port NLDO1  [also labelled VDD_0V75_S3]
NLDO2: C169.1 TP28.1(TP) U5.12(NLDO2) ; port NLDO2  [also labelled VDD_DDR_PLL_S0]
NLDO3: C171.1 TP29.1(TP) U5.11(NLDO3) ; port NLDO3  [also labelled HDMI_VDDA0V85_S0]
NLDO4: C172.1 TP27.1(TP) U5.10(NLDO4) ; port NLDO4  [also labelled VDDA_0V85_S0]
NLDO5: C167.1 U5.8(NLDO5) ; port NLDO5  [also labelled VDD_0V75_S0]
PLDO4: C177.2 TP35.1(TP) U5.63(PLDO4) ; port PLDO4  [also labelled VCCA_3V3_S0]
PLDO5: C178.2 U5.65(PLDO5) ; port PLDO5  [also labelled VCCIO_SD_S0]
VCC1: C49.1 C50.1 C59.1 C60.1 C68.1 C75.1 C77.1 C161.1 C173.1 C175.1 C179.1 C552.1 C558.2 D1.1 TP15.1(TP) TP37.1(TP) U5.1(VCC9) U5.7(VCC8) U5.21(VCCA) U5.22(VCC4) U5.27(VCC10) U5.28(VCC6) U5.33(VCC2) U5.34(VCC2) U5.43(VCC7) U5.44(VCC5) U5.52(VCC1) U5.53(VCC1) U5.54(VCC3) U5.64(VCC12) ; port VCC9, port VCC3, port VCC4, port VCC5, port VCC6, port VCC7, port VCC8, port VCC10  [also labelled VCC10, VCC2, VCC3, VCC4, VCC4V0_SYS, VCC5, VCC6, VCC7, VCC8, VCC9]
VCC1V8_PMU_DDR_S3: R30.1 R31.1 TP18.1(TP)
VCC14: C176.2 TP38.1(TP) U5.9(VCC14) ; port VCC14  [also labelled VCC_1V1_NLDO_S3]
VCC_1V8_S0: C556.2 U5.58(PLDO2)
VCC_1V8_S3: C63.1 C64.1 L4.1 R31.2 R41.2 R172.2 TP39.1(TP) U5.25(VOUT10) ; port VOUT10  [also labelled VOUT10]  [project net VCCQ]
VCC_1V8_S3_PLDO6: C174.1 R30.2 U5.20(VCCIO)
VCC_2V0_PLD0_S3: C637.1 R292.2 R293.2
VCC_2V0_PLDO_S3: C553.1 C554.1 U5.13(VCC13) U5.59(VCC11)
VCC_3V3_S3: C73.1 C74.1 L10.1 TP22.1(TP) U5.5(VOUT8) ; port VOUT8  [also labelled VOUT8]  [project net EMMC_VCC]
VCCA_1V8_S0: C555.2 U5.60(PLDO1)  [project net VCCA_1V8]
VDD_CPU_LIT_S0: C62.2 C442.1 R34.1 R286.2 R287.2 U5.37(VOUT2) ; port VOUT2  [also labelled VOUT2]
VDD_DDR_S0: C46.1 C51.2 R29.2 R148.2 R149.2 U5.46(VOUT5) ; port VOUT5  [also labelled VOUT5]
VDD_GPU_S0: C350.1 R247.2 R248.2
VDD_LOG_S0: C157.2 C444.1 R36.1 R288.2 R289.2 U5.56(VOUT3) ; port VOUT3  [also labelled VOUT3]
VDD_VDENC_S0: C163.2 C446.1 R38.1 R290.2 R291.2 U5.24(VOUT4) ; port VOUT4  [also labelled VOUT4]
VDDA_1V2_S0: C557.2 U5.57(PLDO3)
VOUT6: C55.1 C56.1 C57.1 C58.1 L3.2 R32.2 TP14.1(TP) U5.30(VOUT6) ; port VOUT6  [also labelled VDD2_DDR_S3]
VOUT9: C69.1 C70.1 C71.1 C72.1 L7.2 R35.2 U5.67(VOUT9) ; port VOUT9  [also labelled VDDQ_DDR_S0]
PMIC_EXT_EN_OUT: U5.39(EXT_EN) ; port PMIC_EXT_EN_OUT
PMIC_FB6: C55.2 R32.1 R33.2
PMIC_FB9: C69.2 R35.1 R37.2 U5.66(FB9) ; port PMIC_FB9
PMIC_INT_L: R41.1 U5.19(INT) ; port PMIC_INT_L
PMIC_PWR_CTRL1: U5.62(PWRCRTL1) ; port PMIC_PWR_CTRL1
PMIC_PWR_CTRL2: U5.61(PWRCRTL2) ; port PMIC_PWR_CTRL2
PMIC_SPI_CLK: U5.17(CLK/SCL) ; port PMIC_SPI_CLK
PMIC_SPI_CS: U5.18(CS) ; port PMIC_SPI_CS
PMIC_SPI_MOSI: U5.15(MOSI) ; port PMIC_SPI_MOSI
PMIC_SW1: L1.1 U5.50(SW1) U5.51(SW1)
PMIC_SW2: L5.1 U5.35(SW2) U5.36(SW2)
PMIC_SW3: L11.1 U5.55(SW3) ; port PMIC_SW3
PMIC_SW4: L12.1 U5.23(SW4) ; port PMIC_SW4
PMIC_SW5: L2.1 U5.45(SW5) ; port PMIC_SW5
PMIC_SW6: L3.1 U5.29(SW6) ; port PMIC_SW6
PMIC_SW7: L13.1 U5.42(SW7) ; port PMIC_SW7
PMIC_SW8: L10.2 U5.6(SW8) ; port PMIC_SW8
PMIC_SW9: L7.1 U5.68(SW9) ; port PMIC_SW9
PMIC_SW10: L4.2 U5.26(SW10) ; port PMIC_SW10
PMIC_VDC: C314.2 R39.1 R40.1 U5.32(VDC)
PWRON_L: C170.2 U5.4(PWRON) ; port PWRON_L
RESET_L: R172.1 U5.40(~{RESET}) ; port RESET_L
VDD_GPIO_S0: C45.2 R28.1 U5.49(VOUT1) ; port VOUT1  [also labelled VOUT1]
VOUT7: C180.1 C181.1 L13.2 R292.1 R293.1 TP36.1(TP) U5.41(VOUT7) ; port VOUT7
NetC41_1: C41.1 C42.1 C43.2 C44.2 C45.1 L1.2 R28.2 R247.1 R248.1 TP10.1(TP)
NetC51_1: C51.1 C52.1 C53.1 C54.1 L2.2 R29.1 R148.1 R149.1 TP13.1(TP)
NetC61_1: C61.1 C62.1 C65.1 C66.1 C67.1 L5.2 R34.2 R286.1 R287.1 TP17.1(TP)
NetC76_1: C76.1 C157.1 C158.1 C159.1 C160.1 L11.2 R36.2 R288.1 R289.1 TP25.1(TP)
NetC162_1: C162.1 C163.1 C164.1 C165.1 C166.1 L12.2 R38.2 R290.1 R291.1 TP31.1(TP)
NetC179_2: C179.2 D2.1(C) R39.2

Not connected (* = marked no-connect by the designer): U5 2(SYNC)* 3(SYNC_CLK)* 16(MISO) 31(FB6)* 38(FB2) 47(FB5)* 48(FB1)

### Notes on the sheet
- 0V75
- 0V85
- 1V8
- 1V2

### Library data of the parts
C41 C42 C46 C53 C54 C56 C57 C61 C63-C67 C70 C71 C73 C74 C76 C158-C160 C162 C164-C166 C180 C181 = CMP-06035-006914-1: Chip Multilayer Ceramic Capacitors for General Purpose, 0603, 22uF, X5R, 15%, 20%, 6.3V
C43 C44 = CMP-1036-04949-2: Manufacturer: Kemet; Part Number: C0805C476M7PACTU
C45 C51 C62 C157 C163 C174 C175 C177 C178 C553-C558 = CMP-2008-02081-2: CAP CER 1UF 10V X5R 0402; Dielectric Material: Ceramic; Dissipation Factor: 5%; Tolerance: 10%
C49 C52 C58-C60 C72 C75 C77 C350 C442 C444 C446 C637 = CMP-00621-81932632-1: CC0603KRX5R7BB106 Multilayer Ceramic Capacitor, 10 uF, 16 V, ± 10%, X5R, 0603 [1608 Metric]; Capacitance: 10µF; Voltage Rating: 16V
C50 C68 C161 C173 C552 = CMP-03020-034697-1: CAP CER 22UF 10V X5R 0805; Tolerance: 20%; Dissipation Factor: 10%; Dielectric Material: Ceramic
C55 C69 = CMP-2008-03415-2: Cap Ceramic 100pF 50V C0G 5% Pad SMD 0402 125C Automotive T/R; Manufacturer Part Number: C0402C101J5GACAUTO; Manufacturer: Kemet; Temperature Coefficient: 15%; Tolerance: 0.05
C167-C169 C171 C172 = CMP-03422-000732-3: CAP CER 2.2UF 16V X5R 0402; Tolerance: 10%
C170 C314 = CMP-2008-01247-1: Manufacturer: Vitramon; Part Number: VJ0402Y102KXXPW1BC
C176 = CMP-03422-000660-2: as C284 on sheet rk3588_LPDDR4
C179 = CMP-03422-000819-1: CAP CER 4.7UF 16V X5R 0402; Manufacturer Part Number: CC0402MRX5R7BB475; Manufacturer: YAGEO; Tolerance: 0.2; Automotive Grade: NA; Material: Ceramic; Temperature Coefficient: 30ppm/°C
D1 = CMP-08607-000062-1: TVS DIODE 7V 10V 0402; Manufacturer: Littelfuse; Value: 0.1pF; Breakdown Voltage: 9.8V; Number Of Channels: 1; Peak Pulse Current: 2A; Direction: Bidirectional; Automotive Grade: Grade 1; Standoff Height: 0mm
D2 = CMP-07163-000040-1: DIODE GEN PURP 75V 150MA SOD323F; Forward Voltage: 1V; Power Dissipation: 200mW; Element Configuration: Single; Max Forward Surge Current (Ifsm): 2A; Peak Reverse Current: 5uA; Recovery Time: 4ns
L1 L5 L11 L12 = CMP-06042-016508-1: FIXED IND
L2-L4 L7 L10 L13 = CMP-14484-000922-1: Inductor Power Shielded Wirewound 0.47uH 30% 100KHz Ferrite 5A 13mΩ DCR Automotive T/R; DC Resistance (DCR): 13mR; Saturation Current: 9A; Inductance: 470nH; Self Resonant Frequency: 185MHz
R28 R29 R34 R36 R38 = CMP-02407-010762-1: RES SMD 1.2K OHM 1% 1/10W 0402; Voltage Rating: 50V; Max Power Dissipation: 100mW; Temperature Coefficient: 50ppm/°C
R30 R31 = CMP-03412-047152-1: Anti-Sulfurated Chip Resistor Automotive Grade 0Ω Jumper 0.125W 0805; Max Power Dissipation: 125mW
R32 = CMP-2002-07855-1: Manufacturer: Yageo; Part Number: RC0402FR-13120KL
R33 R37 = CMP-03211-001392-1: 100k 0402; Manufacturer Part Number: CRGP0402F100K; Manufacturer: TE; Value: 100KΩ; Power Rating: 0.125W; Tolerance: 0.01; Temperature Coefficient: ±100ppm/°C; Voltage Rating: 50V
R35 = CMP-2002-05709-1: 20k 0402 1%; Manufacturer: TE Connectivity / AMP; Part Number: CRG0402F20K
R39 R40 = CMP-03412-037959-1: RES 200kΩ ±5% 0.063W 0402; Power Rating: 62.5mW; Max Power Dissipation: 63mW; Resistance: 200kR; Temperature Coefficient: 100ppm/°C; Voltage Rating: 50V
R41 R172 = CMP-2002-01682-1: Manufacturer: Vishay BCcomponents; Part Number: TNPW040210K0DEED
R148 R247 R286 R288 R290 R292 = CMP-009-00002-5: DNP; Voltage Rating: 200V; Power: 250mW
R149 R248 R287 R289 R291 R293 = CMP-009-00002-5: 10mΩ 1W Current Sense Resistor SMD ±1% ±100ppm/℃ 1206 Current Sense Resistors / Shunt Resistors ROHS; Tolerance: 5%; Voltage Rating: 200V
TP10 TP13-TP15 TP17 TP18 TP22 TP25 TP27-TP29 TP31 TP35-TP39 = CMP-00028-00002-2: 0.6mm round
U5 = RK806-1: RK806-1 Power Management IC; MF: rockchip

## Sheet ATE_Safety.SchDoc
size A; SheetNumber: 5; SheetTotal: 22
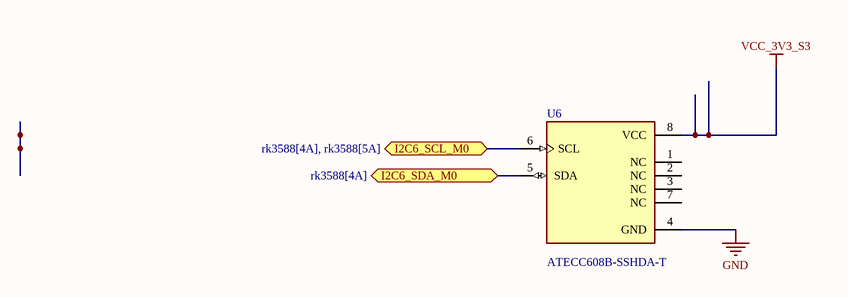
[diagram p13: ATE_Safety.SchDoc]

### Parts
U6  ATECC608B-SSHDA-T  [SOIC127P600X175-8N]

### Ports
I2C6_SCL_M0 (bidir, see rk3588[4A], rk3588[5A]), I2C6_SDA_M0 (bidir, see rk3588[4A])

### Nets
GND: U6.4(GND)
VCC_3V3_S3: U6.8(VCC)  [project net EMMC_VCC]
I2C6_SCL_M0: U6.6(SCL) ; port I2C6_SCL_M0
I2C6_SDA_M0: U6.5(SDA) ; port I2C6_SDA_M0

Not connected (* = marked no-connect by the designer): U6 1(NC) 2(NC) 3(NC) 7(NC)

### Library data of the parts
U6 = ATECC608B-SSHDA-T: Security ICs / Authentication ICs ECC/ECDH, I2C, SOIC T/R; MF: Microchip Technology

## Sheet SPI _NOR.SchDoc
size A; SheetNumber: 6; SheetTotal: 22
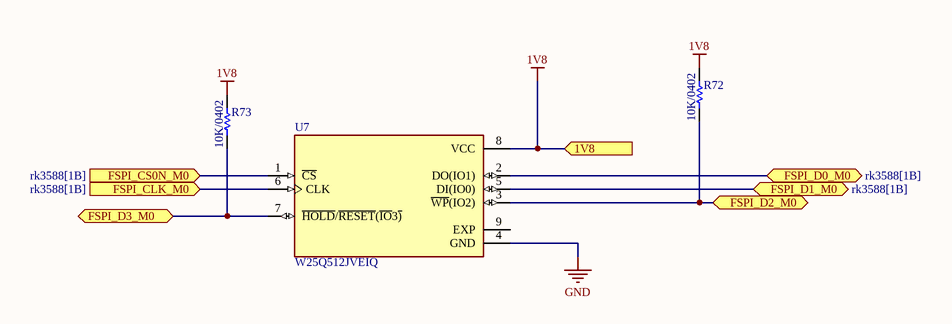
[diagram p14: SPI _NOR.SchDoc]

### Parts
R72  10K/0402  [RESC1005X40X20NL05T10]
R73  10K/0402  [RESC1005X40X20NL05T10]
U7  W25Q512JVEIQ  [SON127P600X800X80-9N]

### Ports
1V8 (in), FSPI_CLK_M0 (in, see rk3588[1B]), FSPI_CS0N_M0 (in, see rk3588[1B]), FSPI_D0_M0 (bidir, see rk3588[1B]), FSPI_D1_M0 (bidir, see rk3588[1B]), FSPI_D2_M0 (bidir), FSPI_D3_M0 (bidir)

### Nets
1V8: R72.2 R73.2 U7.8(VCC) ; port 1V8
GND: U7.4(GND)
FSPI_CLK_M0: U7.6(CLK) ; port FSPI_CLK_M0
FSPI_CS0N_M0: U7.1(~{CS}) ; port FSPI_CS0N_M0
FSPI_D0_M0: U7.2(DO(IO1)) ; port FSPI_D0_M0
FSPI_D1_M0: U7.5(DI(IO0)) ; port FSPI_D1_M0
FSPI_D2_M0: R72.1 U7.3(~{WP}(IO2)) ; port FSPI_D2_M0
FSPI_D3_M0: R73.1 U7.7(~{HOLD}/~{RESET}(~{IO}3~{)}) ; port FSPI_D3_M0

Not connected (* = marked no-connect by the designer): U7 9(EXP)

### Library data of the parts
R72 R73 = CMP-2002-01682-1: as R41 on sheet RK806-1
U7 = W25Q512JVEIQ: FLASH - NOR Memory IC 512Mb (64M x 8) SPI - Quad I/O 133 MHz 8-WSON (8x6); MF: Winbond Electronics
